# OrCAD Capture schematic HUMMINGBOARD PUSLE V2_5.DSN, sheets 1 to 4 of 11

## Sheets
1 POWER: size C; title: POWER; rev: 2.5.0
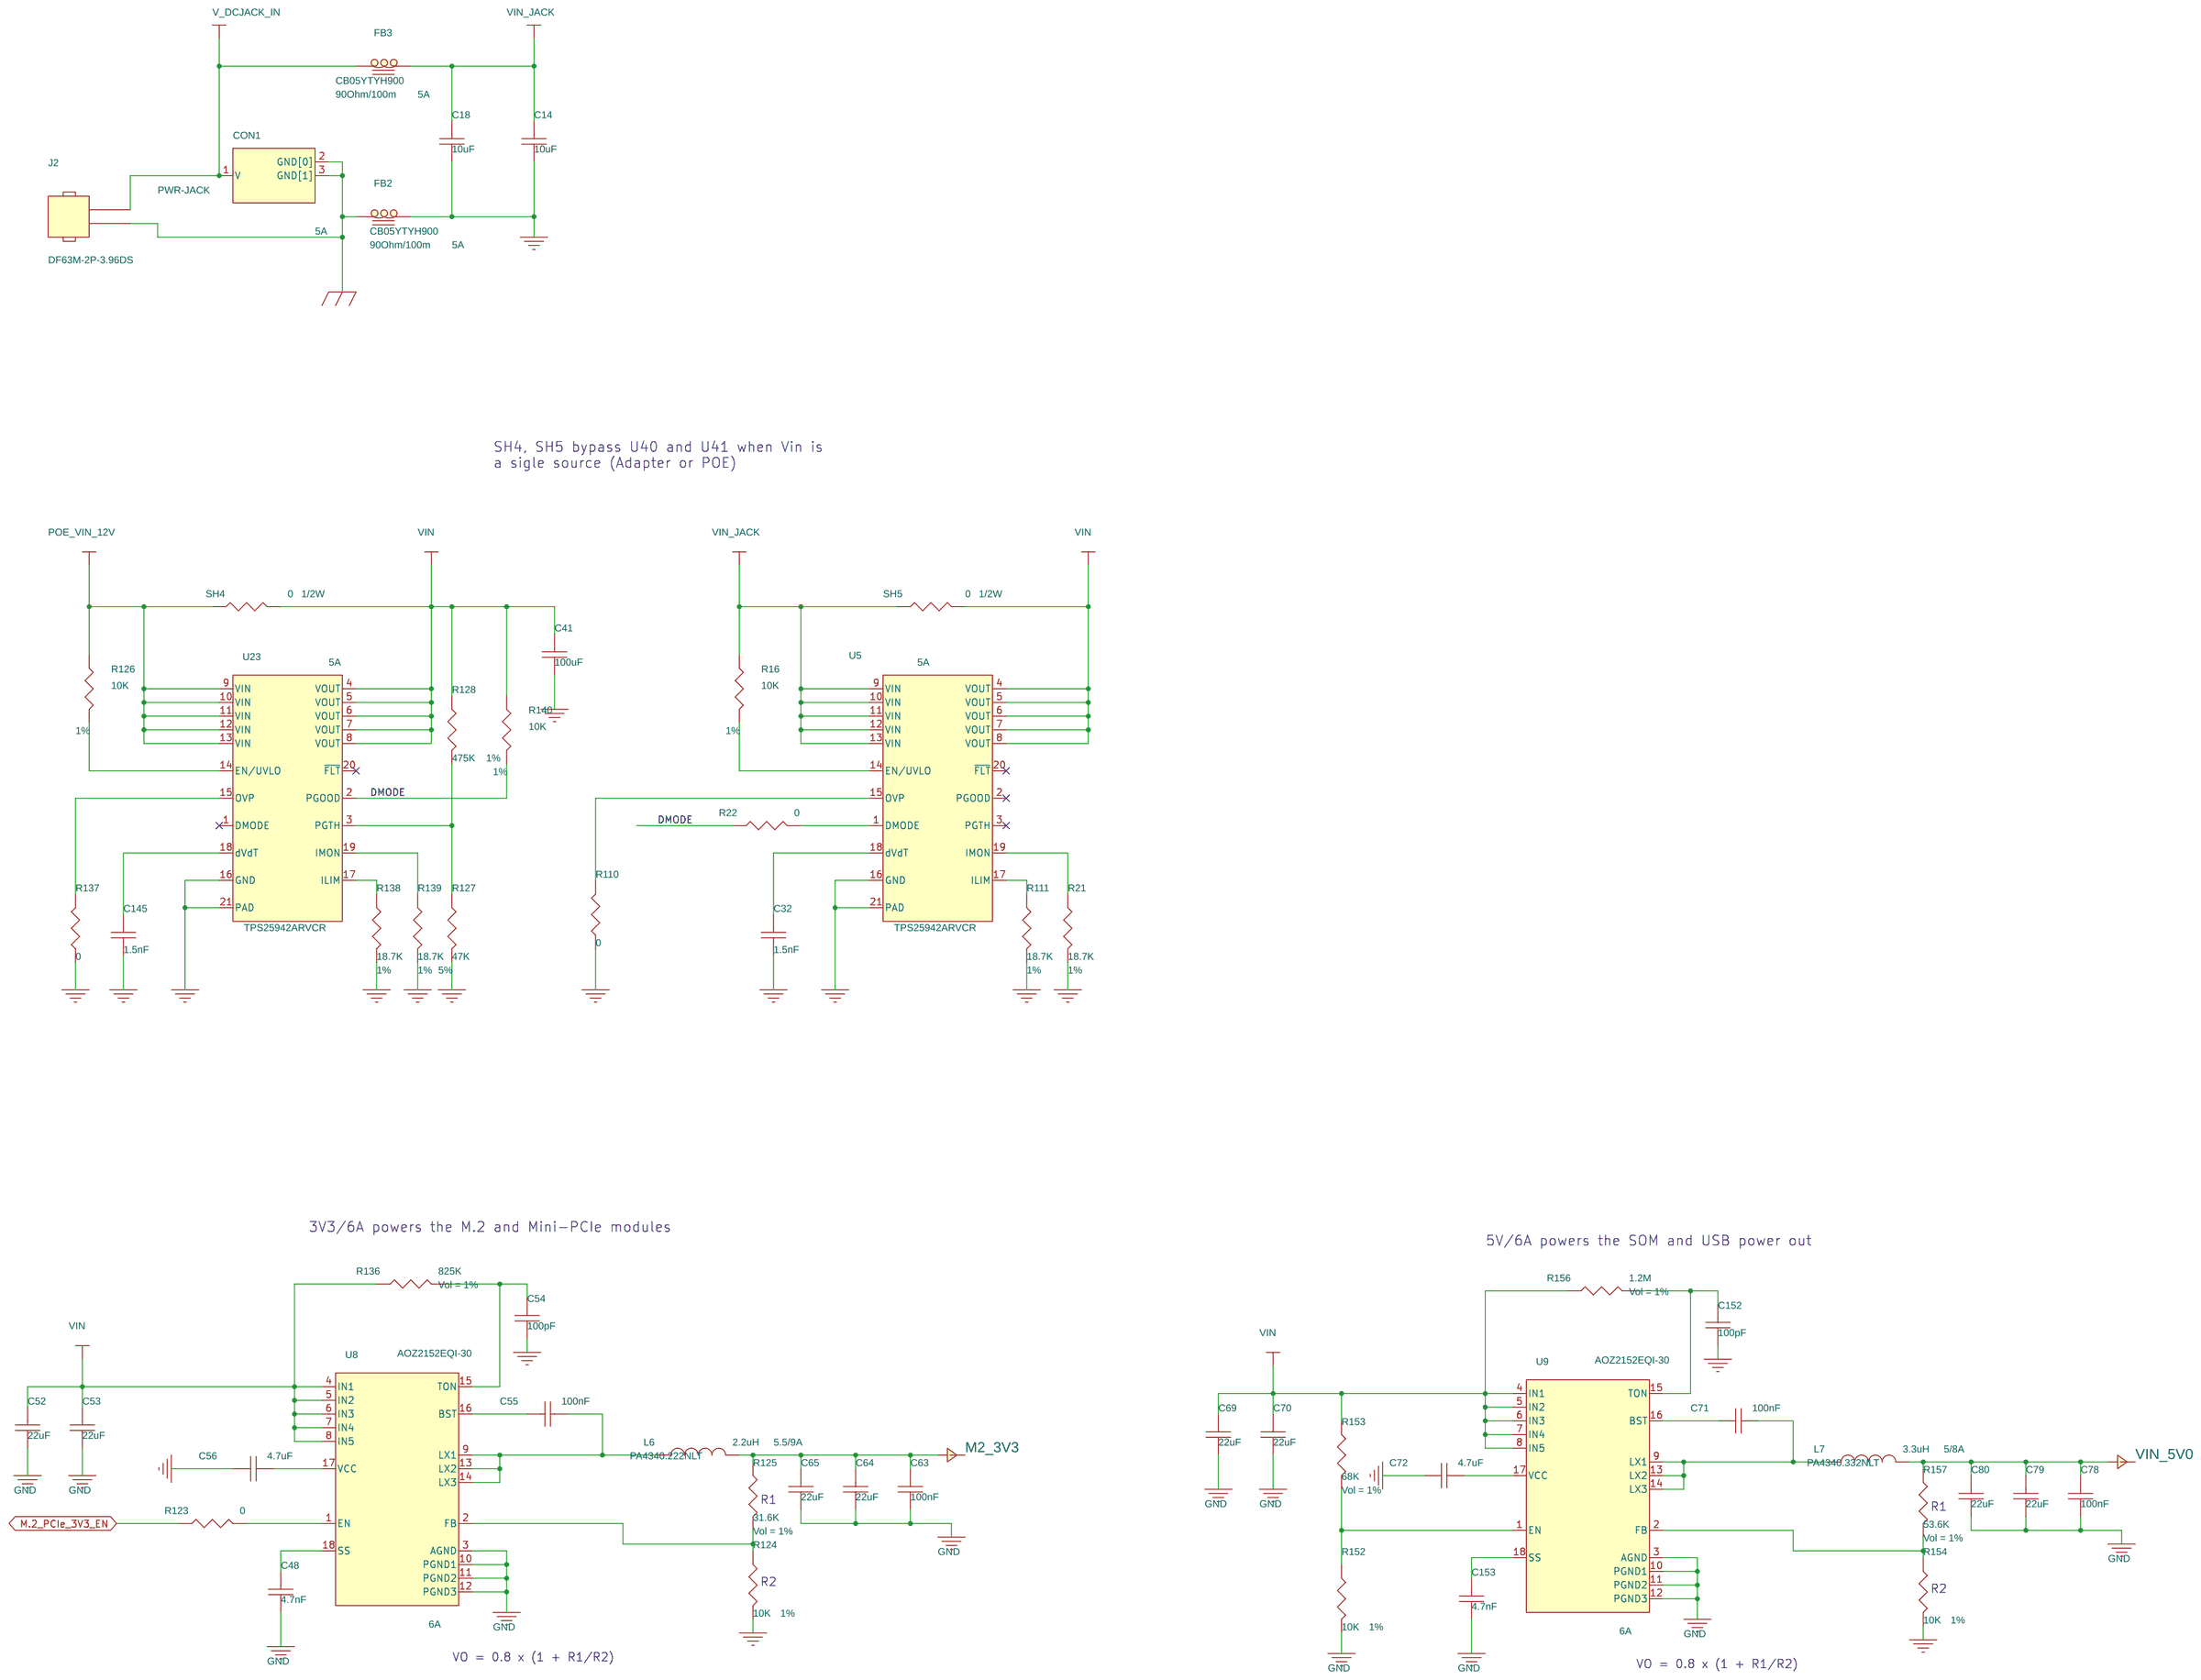
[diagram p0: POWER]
2 SYSTEM, ETHERNET, UART: size A3; title: SYSTEM,  DEBUG, uSD, EEPROM
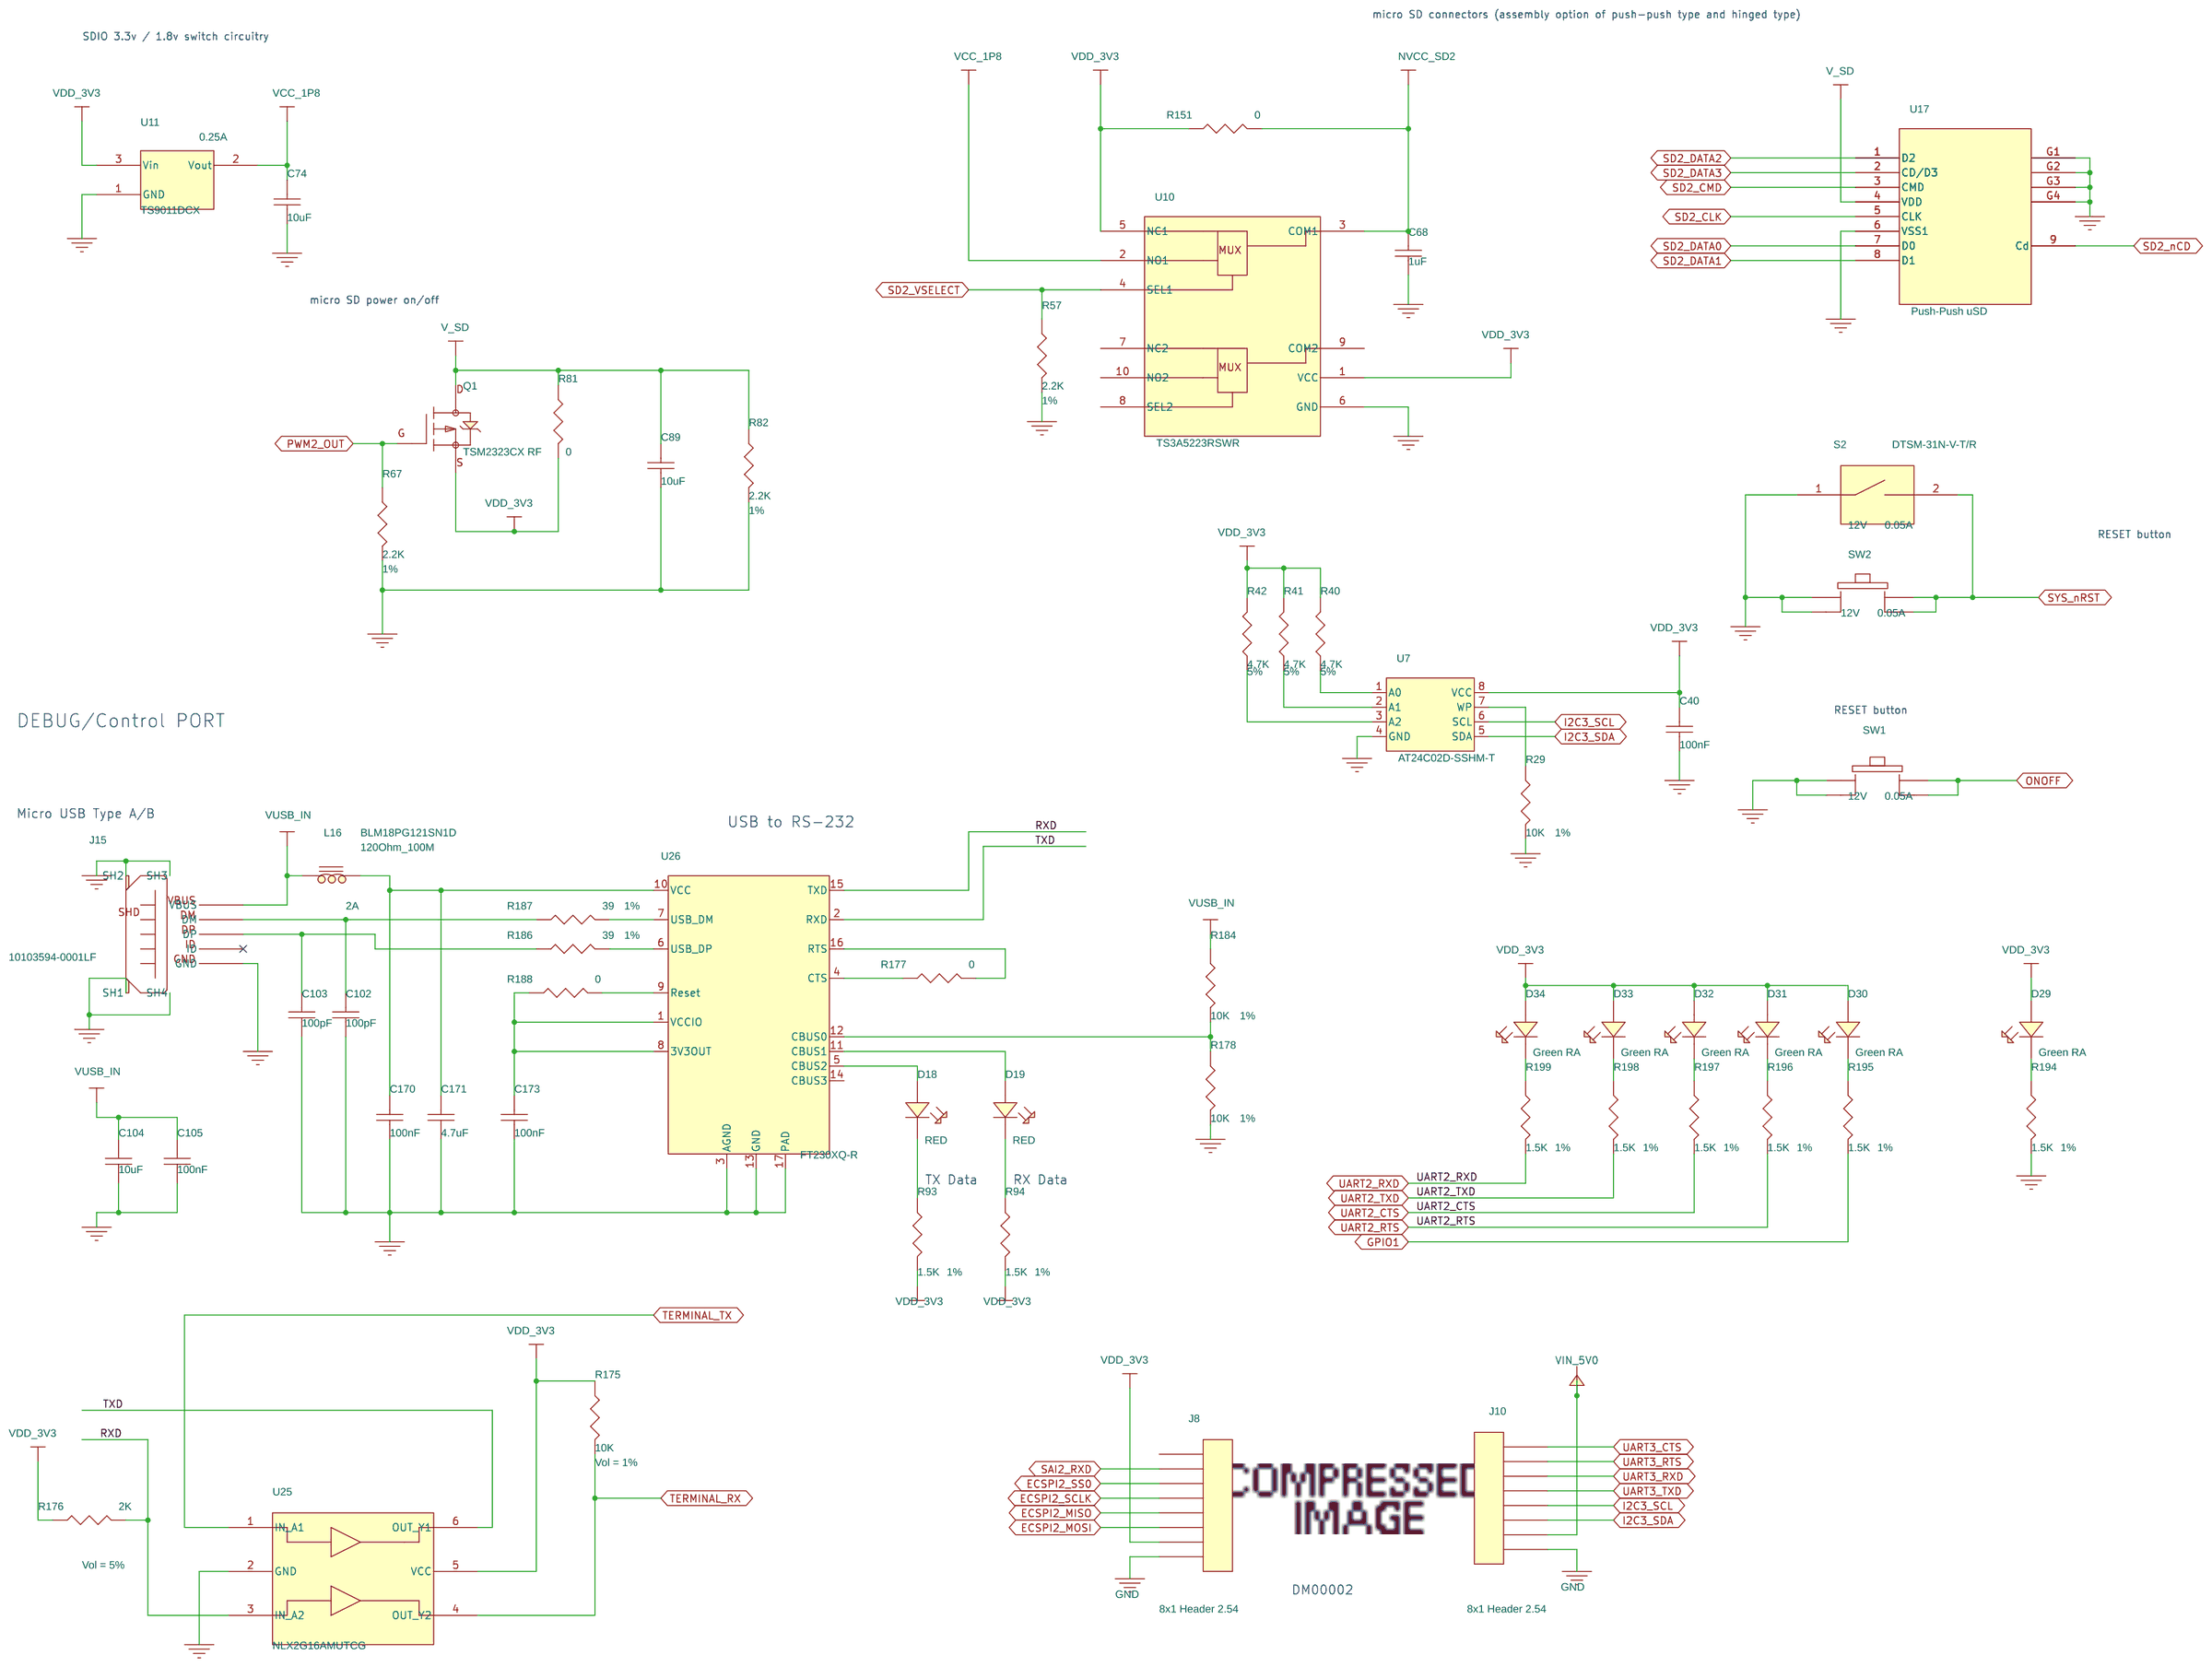
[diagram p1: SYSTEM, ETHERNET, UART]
3 PCIe, M.2, RTC: size A3; title: PCIE, M.2, RTC, IR
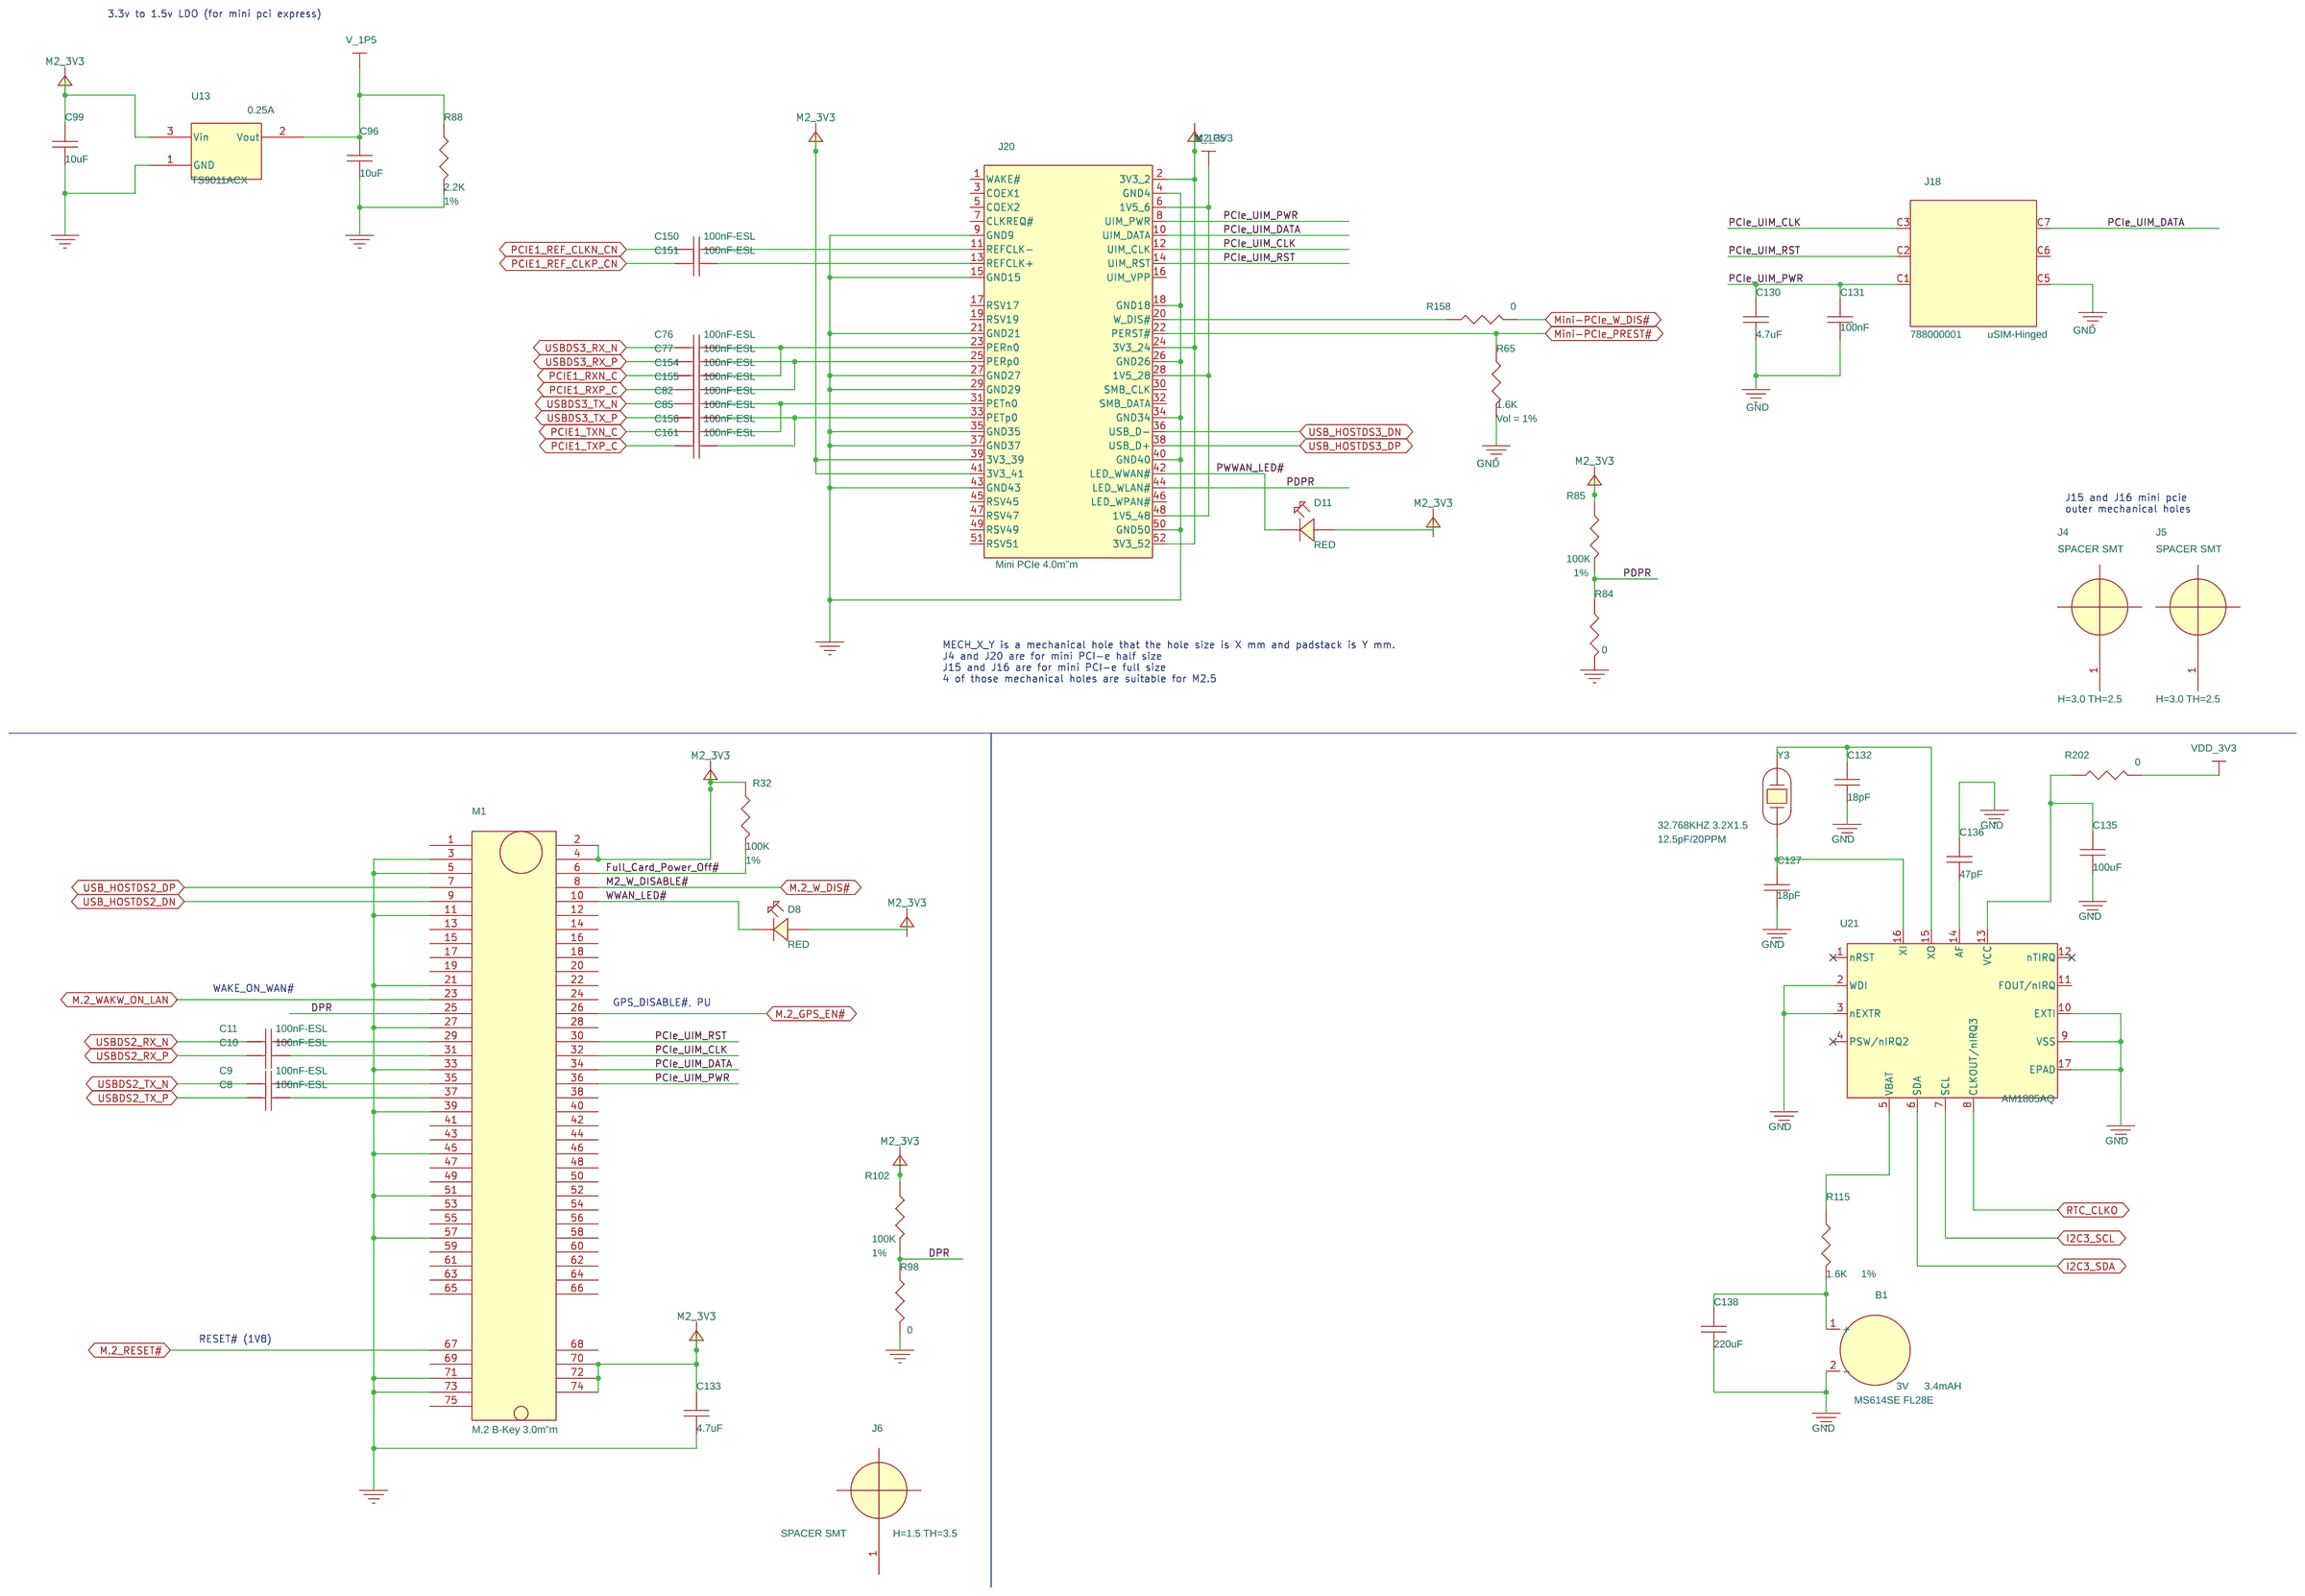
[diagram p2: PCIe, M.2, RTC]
4 USB HUB: size C; title: USB-3 HIB; rev: 2.4.0
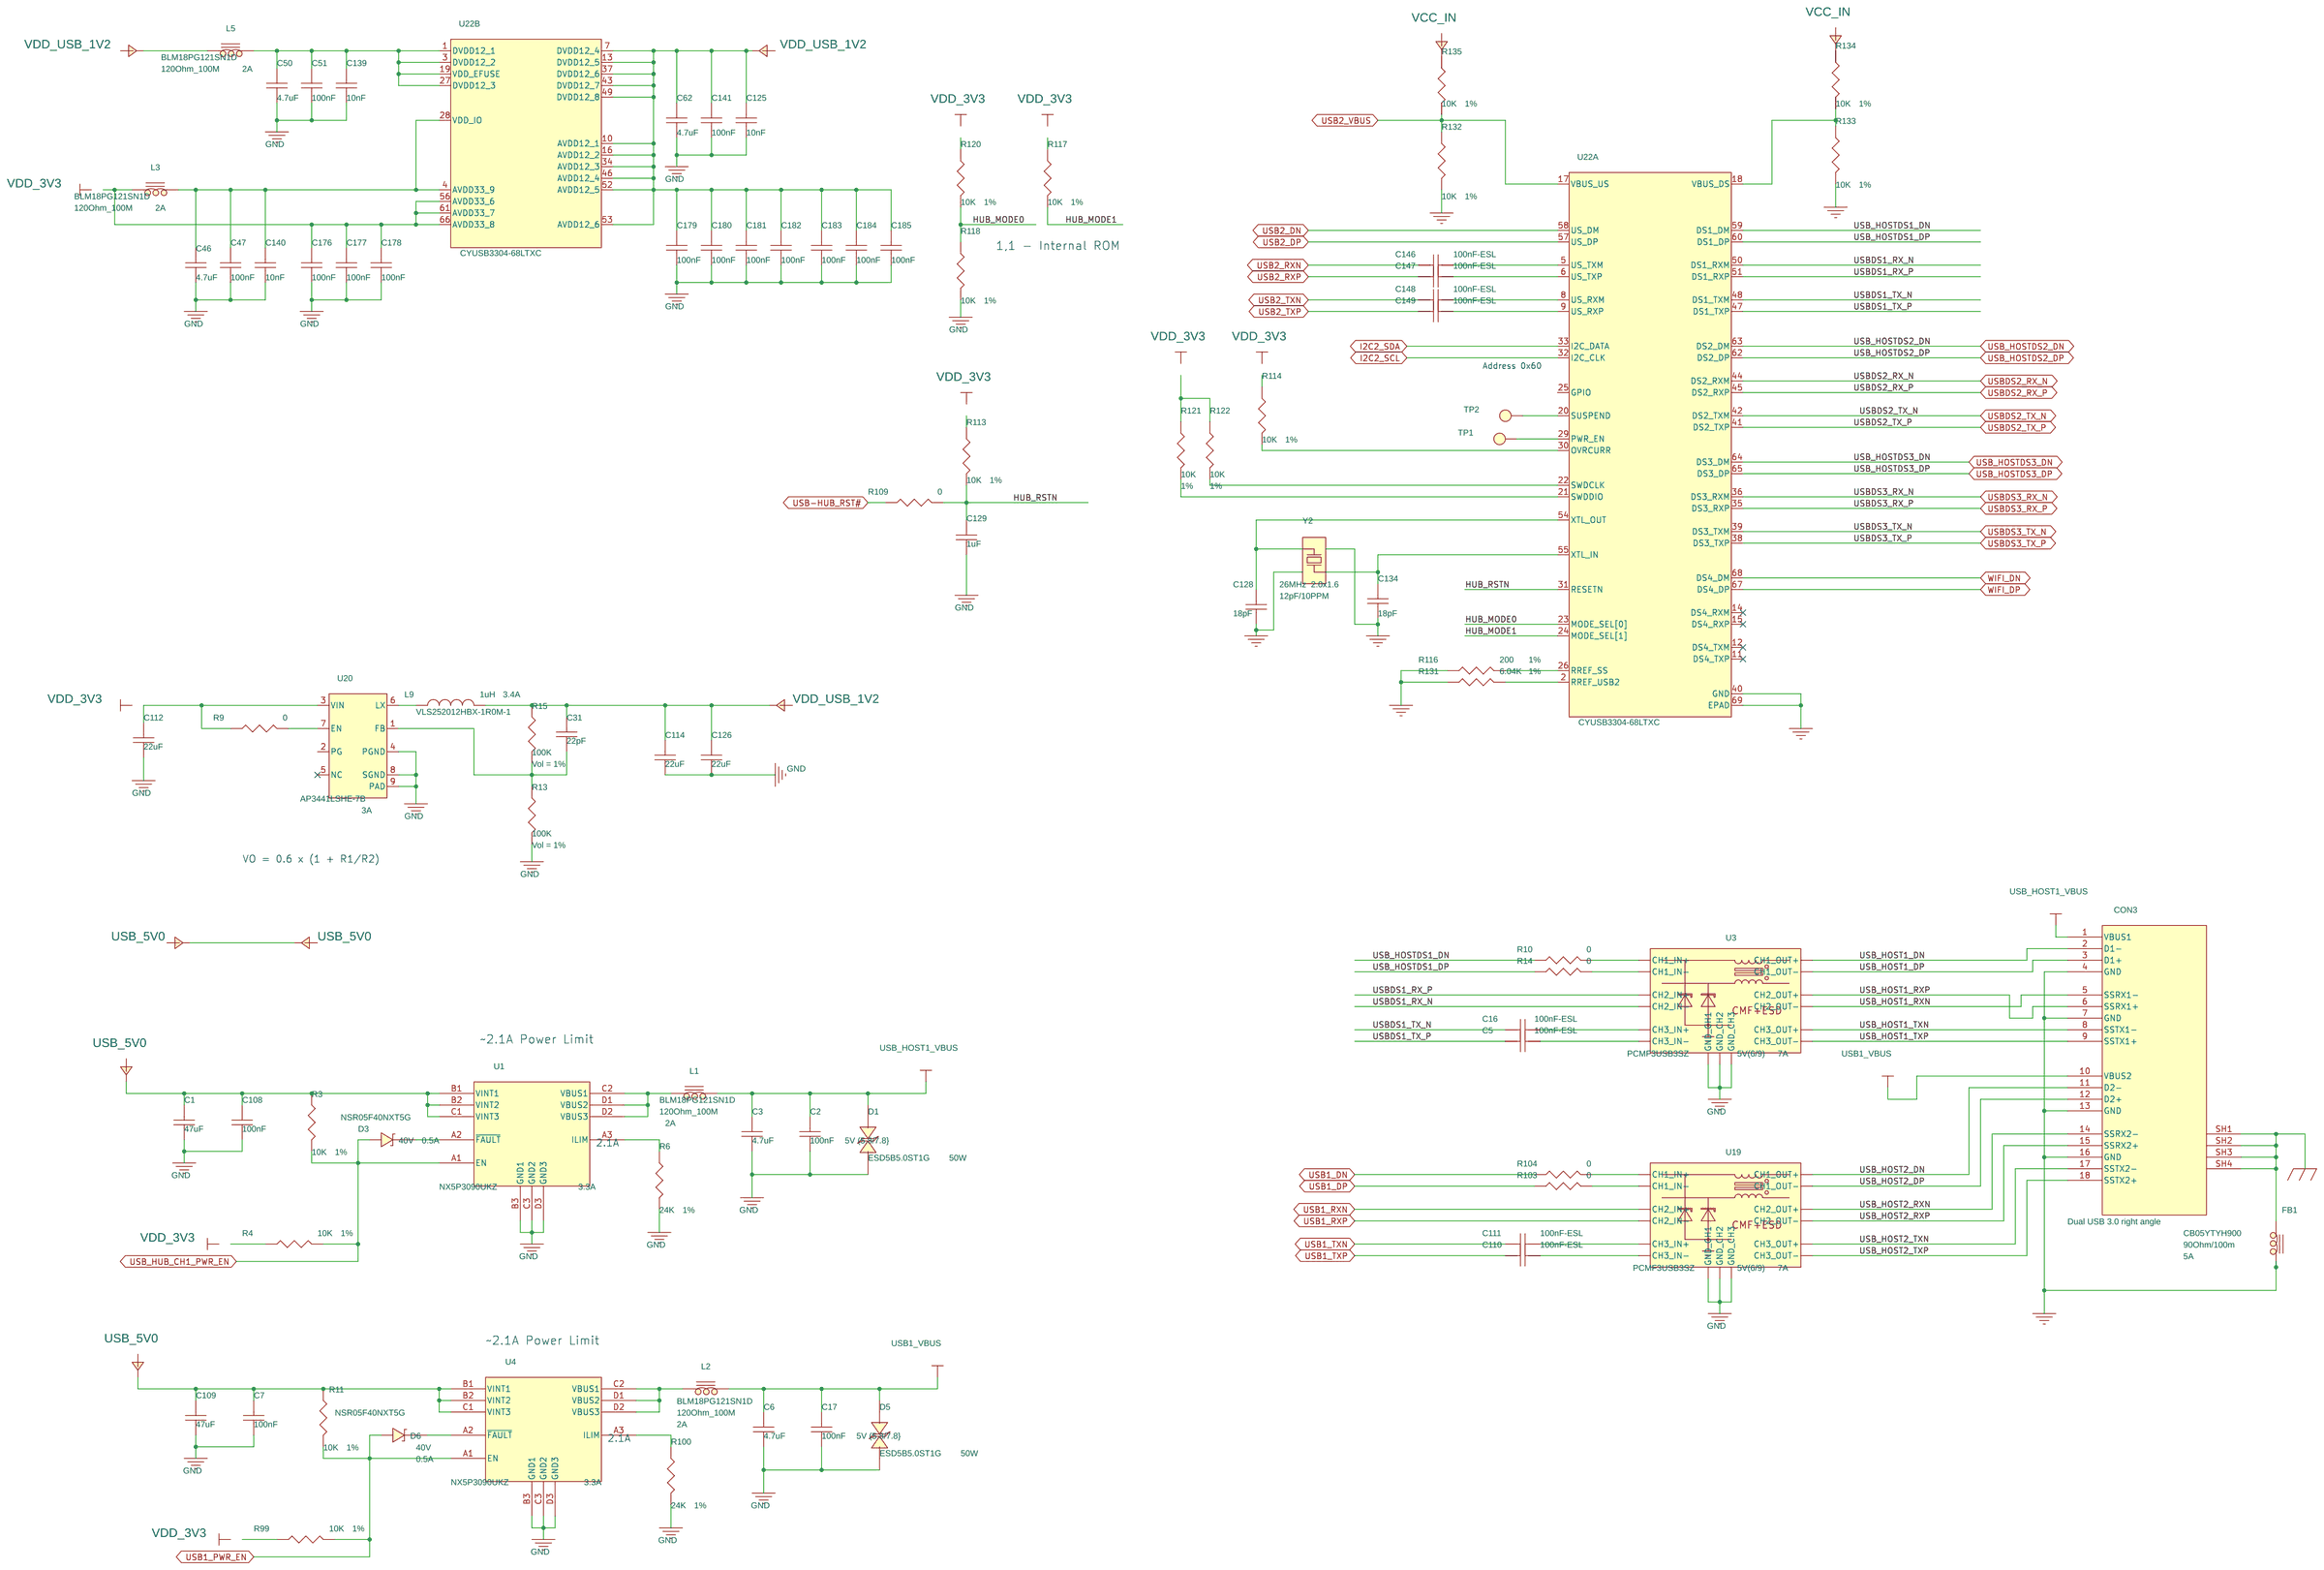
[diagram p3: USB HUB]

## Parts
sheet PCIe, M.2, RTC
B1  MS614SE FL28E  [MS614SE FL28E]
C8  100nF-ESL  [C0402]
C9  100nF-ESL  [C0402]
C10  100nF-ESL  [C0402]
C11  100nF-ESL  [C0402]
C76  100nF-ESL  [C0402]
C77  100nF-ESL  [C0402]
C82  100nF-ESL  [C0402]
C85  100nF-ESL  [C0402]
C96  10uF  [C0603]
C99  10uF  [C0603]
C127  18pF  [C0402]
C130  4.7uF  [C0603]
C131  100nF  [C0402]
C132  18pF  [C0402]
C133  4.7uF  [C0603]
C135  100uF  [C1210]
C136  47pF  [C0402]
C138  220uF  [C1210]
C150  100nF-ESL  [C0402]
C151  100nF-ESL  [C0402]
C154  100nF-ESL  [C0402]
C155  100nF-ESL  [C0402]
C156  100nF-ESL  [C0402]
C161  100nF-ESL  [C0402]
D8  RED  [1SA0603S11A0CB01]
D11  RED  [1SA0603S11A0CB01]
J4  SPACER SMT
J5  SPACER SMT
J6  SPACER SMT
J18  788000001  [788000001]
J20  Mini PCIe 4.0m"m  [MM60-52B1-G1-R850]
M1  M.2 B-Key 3.0m"m  [AS0BC21-S30BB-7H]
R32  100K  [R0402]
R65  1.6K  [R0402]
R84  0  [R0402]
R85  100K  [R0402]
R88  2.2K  [R0402]
R98  0  [R0402]
R102  100K  [R0402]
R115  1.6K  [R0402]
R158  0  [R0402]
R202  0  [R0603]
U13  TS9011ACX  [TS9011ACX]
U21  AM1805AQ  [AM1805AQ]
Y3  32.768KHZ 3.2X1.5  [NX3215SA32.768K-STD-MUA-4]
sheet POWER
C14  10uF  [C1206]
C18  10uF  [C1206]
C32  1.5nF  [C0402]
C41  100uF  [C1210]
C48  4.7nF  [C0402]
C52  22uF  [C1206]
C53  22uF  [C1206]
C54  100pF  [C0402]
C55  100nF  [C0402]
C56  4.7uF  [C0603]
C63  100nF  [C0402]
C64  22uF  [C0603]
C65  22uF  [C0603]
C69  22uF  [C1206]
C70  22uF  [C1206]
C71  100nF  [C0402]
C72  4.7uF  [C0603]
C78  100nF  [C0402]
C79  22uF  [C0603]
C80  22uF  [C0603]
C145  1.5nF  [C0402]
C152  100pF  [C0402]
C153  4.7nF  [C0402]
CON1  PWR-JACK  [KLDHCX-0202-A-LT]
FB2  CB05YTYH900  [CB05YTYH900]
FB3  CB05YTYH900  [CB05YTYH900]
J2  DF63M-2P-3.96DS  [DF63M-2P-3.96DS]
L6  PA4340.222NLT  [PA4340.222NLT]
L7  PA4340.332NLT  [PA4340.332NLT]
R16  10K  [R0402]
R21  18.7K  [R0402]
R22  0  [R0402]
R110  0  [R0402]
R111  18.7K  [R0402]
R123  0  [R0402]
R124  10K  [R0402]
R125  31.6K  [R0402]
R126  10K  [R0402]
R127  47K  [R0402]
R128  475K  [R0402]
R136  825K  [R0402]
R137  0  [R0402]
R138  18.7K  [R0402]
R139  18.7K  [R0402]
R140  10K  [R0402]
R152  10K  [R0402]
R153  68K  [R0402]
R154  10K  [R0402]
R156  1.2M  [R0402]
R157  53.6K  [R0402]
SH4  0  [R0603]
SH5  0  [R0603]
U5  TPS25942ARVCR  [TPS25942ARVCR]
U8  AOZ2152EQI-30  [AOZ2152EQI-30]
U9  AOZ2152EQI-30  [AOZ2152EQI-30]
U23  TPS25942ARVCR  [TPS25942ARVCR]
sheet SYSTEM, ETHERNET, UART
C40  100nF  [C0402]
C68  1uF  [C0402]
C74  10uF  [C0603]
C89  10uF  [C0603]
C102  100pF  [C0402]
C103  100pF  [C0402]
C104  10uF  [C0603]
C105  100nF  [C0402]
C170  100nF  [C0402]
C171  4.7uF  [C0603]
C173  100nF  [C0402]
D18  RED  [1SA0603S11A0CB01]
D19  RED  [1SA0603S11A0CB01]
D29  Green RA  [APA2106CGCK]
D30  Green RA  [APA2106CGCK]
D31  Green RA  [APA2106CGCK]
D32  Green RA  [APA2106CGCK]
D33  Green RA  [APA2106CGCK]
D34  Green RA  [APA2106CGCK]
J8  8x1 Header 2.54  [CH31082V200-NH]
J10  8x1 Header 2.54  [CH31082V200-NH]
J15  10103594-0001LF  [10103594-0001LF]
L16  BLM18PG121SN1D  [BLM18PG121SN1D]
Q1  TSM2323CX RF  [TSM2323CX RF]
R29  10K  [R0402]
R40  4.7K  [R0402]
R41  4.7K  [R0402]
R42  4.7K  [R0402]
R57  2.2K  [R0402]
R67  2.2K  [R0402]
R81  0  [R0402]
R82  2.2K  [R0402]
R93  1.5K  [R0402]
R94  1.5K  [R0402]
R151  0  [R0402]
R175  10K  [R0402]
R176  2K  [R0402]
R177  0  [R0402]
R178  10K  [R0402]
R184  10K  [R0402]
R186  39  [R0402]
R187  39  [R0402]
R188  0  [R0402]
R194  1.5K  [R0402]
R195  1.5K  [R0402]
R196  1.5K  [R0402]
R197  1.5K  [R0402]
R198  1.5K  [R0402]
R199  1.5K  [R0402]
S2  DTSM-31N-V-T/R  [DTSM-31N-V-T/R]
SW1  SKSCLDE010  [SKSCLDE010]
SW2  SKSCLDE010  [SKSCLDE010]
U7  AT24C02D-SSHM-T  [AT24C02D-SSHM-B]
U10  TS3A5223RSWR  [TS3A5223RSWR]
U11  TS9011DCX  [TS9011DCX]
U17  Push-Push uSD  [ZM90-15000-0BR1]
U25  NLX2G16AMUTCG  [NLX2G16AMUTCG]
U26  FT230XQ-R  [FT230XQ-R]
sheet USB HUB
C1  47uF  [C1206]
C2  100nF  [C0402]
C3  4.7uF  [C0603]
C5  100nF-ESL  [C0402]
C6  4.7uF  [C0603]
C7  100nF  [C0402]
C16  100nF-ESL  [C0402]
C17  100nF  [C0402]
C31  22pF  [C0402]
C46  4.7uF  [C0603]
C47  100nF  [C0402]
C50  4.7uF  [C0603]
C51  100nF  [C0402]
C62  4.7uF  [C0603]
C108  100nF  [C0402]
C109  47uF  [C1206]
C110  100nF-ESL  [C0402]
C111  100nF-ESL  [C0402]
C112  22uF  [C0603]
C114  22uF  [C0603]
C125  10nF  [C0402]
C126  22uF  [C0603]
C128  18pF  [C0402]
C129  1uF  [C0402]
C134  18pF  [C0402]
C139  10nF  [C0402]
C140  10nF  [C0402]
C141  100nF  [C0402]
C146  100nF-ESL  [C0402]
C147  100nF-ESL  [C0402]
C148  100nF-ESL  [C0402]
C149  100nF-ESL  [C0402]
C176  100nF  [C0402]
C177  100nF  [C0402]
C178  100nF  [C0402]
C179  100nF  [C0402]
C180  100nF  [C0402]
C181  100nF  [C0402]
C182  100nF  [C0402]
C183  100nF  [C0402]
C184  100nF  [C0402]
C185  100nF  [C0402]
CON3  Dual USB 3.0 right angle  [U3AFR03-B-P/L-B-G0-A]
D1  ESD5B5.0ST1G  [ESD5B5.0ST1G]
D3  NSR05F40NXT5G  [NSR05F40NXT5G]
D5  ESD5B5.0ST1G  [ESD5B5.0ST1G]
D6  NSR05F40NXT5G  [NSR05F40NXT5G]
FB1  CB05YTYH900  [CB05YTYH900]
L1  BLM18PG121SN1D  [BLM18PG121SN1D]
L2  BLM18PG121SN1D  [BLM18PG121SN1D]
L3  BLM18PG121SN1D  [BLM18PG121SN1D]
L5  BLM18PG121SN1D  [BLM18PG121SN1D]
L9  VLS252012HBX-1R0M-1  [VLS252012HBX-1R0M-1]
R3  10K  [R0402]
R4  10K  [R0402]
R6  24K  [R0402]
R9  0  [R0402]
R10  0  [R0402]
R11  10K  [R0402]
R13  100K  [R0402]
R14  0  [R0402]
R15  100K  [R0402]
R99  10K  [R0402]
R100  24K  [R0402]
R103  0  [R0402]
R104  0  [R0402]
R109  0  [R0402]
R113  10K  [R0402]
R114  10K  [R0402]
R116  200  [R0402]
R117  10K  [R0402]
R118  10K  [R0402]
R120  10K  [R0402]
R121  10K  [R0402]
R122  10K  [R0402]
R131  6.04K  [R0402]
R132  10K  [R0402]
R133  10K  [R0402]
R134  10K  [R0402]
R135  10K  [R0402]
TP1  R 35
TP2  R 35
U1  NX5P3090UKZ  [NX5P3090UKZ]
U3  PCMF3USB3SZ  [PCMF3USB3SZ]
U4  NX5P3090UKZ  [NX5P3090UKZ]
U19  PCMF3USB3SZ  [PCMF3USB3SZ]
U20  AP3441LSHE-7B  [AP3441LSHE-7B]
U22  CYUSB3304-68LTXC  [CYUSB3304-68LTXC]  (sections A,B)
Y2  26MHz  2.0x1.6  [FA-128 26.0000MF10Z-W5]

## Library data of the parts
B1 = BAT-MS621FE: BATT LITH 3V 3.4MAH COIN 6.8MM; Category : Battery-RCH; Digikey P/N: 728-1055-ND; Manufacturer: Seiko Instruments; Rating: 3.4mAH; SolidRun P/N: BT00007; Vol: 3V; Datasheet: https://www.sii.co.jp/en/me/files/2017/04/MicroBatteryCatalogue-E_2017_web.pdf
C5 C8-C11 C16 C76 C77 C82 C85 C110 C111 C146-C151 C154-C156 C161 = CAP_NP1: CAP CER 0.1uF ±10% 25V X7R 0402; Category : Capacitors (Size: 0402); Manufacturer: CAPAX; Part Num#: 0402X104K250SNT; Rating: 25V; SolidRun P/N: CA20090; Vol: 10%
C74 C89 C96 C99 = CAP_NP1: CAP CER 10uF ±10% 6.3V X5R 0603; Category : Capacitors (Size: 0603); Digikey P/N: 1276-1038-1-ND; Manufacturer: Samsung Electro-Mechanics; Part Num#: CL10A106KQ8NNNC; Rating: 6.3V; SolidRun P/N: CA30001; Vol: 10%
C127 C128 C132 C134 = CAP_NP1: CAP CER 18pF ±1% 50V C0G/NPO 0402; Category : Capacitors (Size: 0402); Digikey P/N: 311-1643-1-ND; Manufacturer: YAGEO; Part Num#: CC0402FRNPO9BN180; Rating: 50V; SolidRun P/N: CA20017; Vol: 1%
C46 C50 C62 C130 C133 = CAP_NP1: CAP CER 4.7uF ±10% 6.3V X5R; Category : Capacitors (Size: 0603); Digikey P/N: 1276-1045-2-ND; Manufacturer: Samsung Electro-Mechanics; Part Num#: CL10A475KQ8NNNC; Rating: 6.3V; SolidRun P/N: CA30003; Vol: 10%
C2 C7 C17 C40 C47 C51 C105 C108 C131 C141 C170 C173 C176-C185 = CAP_NP1: CAP CER 0.1uF ±10% 16V X7R 0402; Category : Capacitors (Size: 0402); Digikey P/N: 1276-1001-1-ND; Manufacturer: Samsung Electro-Mechanics; Part Num#: CL05B104KO5NNNC; Rating: 16V; SolidRun P/N: CA20013; Vol: 10%
C135 = CAP_NP1: CAP CER 100uF ±20% 16V X5R 1210; Category : Capacitors (Size: 0603); Digikey P/N: 311-2052-1-ND; Manufacturer: YAGEO; Part Num#: CC1210MKX5R7BB107; Rating: 16V; SolidRun P/N: CA60008; Vol: 20%
C136 = CAP_NP1: CAP CER 47pF ±5% 50V C0G/NP0 0402; Category : Capacitors (Size: 0402); Digikey P/N: 490-1287-6-ND; Manufacturer: Murata Electronics North America; Part Num#: GRM1555C1H470JZ01D; Rating: 50V; SolidRun P/N: CA20144; Vol: 5%
C138 = CAP_NP1: CAP CER 220uF ±20% 6.3V X5R 1210; Category : Capacitors (Size: 1210); Digikey P/N: 1276-3375-1-ND; Manufacturer: Samsung Electro-Mechanics; Part Num#: CL32A227MQVNNNE; Rating: 6.3V; SolidRun P/N: CA60007; Vol: 20%
D8 D11 D18 D19 = LED: Indication LED 0603 - Red; Category : DI-LED; Manufacturer: BRIGHTEK; Rating: 0.02A; SolidRun P/N: DI00007; Vol: 2V
J4 J5 = SPACER_SMT: SPACER H=3MM TH=2.5; Category : MECH-SPACER; Manufacturer: A-LINK; Part Num#: S0305025A; SolidRun P/N: MCH0006; Vol: H=3.0 TH=2.5; Datasheet: http://www.alink.com.tw/smt%20fastener%20standard%20parts.html
J6 = SPACER_SMT: 1.5mm metal spacer for M.2.5 connector 3.5mm / 5.1mm (3.7mm / 6.0mm hole); Category: MECH-SPACER; Category : MECHANICAL PARTS; Digikey P/N: 732-7068-2-ND; Manufacturer: Wurth Elektronik; Part Num#: WE 977-401-515-1R; SolidRun P/N: MCH0008; Vol: H=1.5 TH=3.5; Datasheet: http://katalog.we-online.de/em/datasheet/9774015151R.pdf
J18 = J-uSIM_CARD_HOLDER_x_6: CONN MICRO SIM CARD HINGED TYPE; Category : CON-Usd/SIM; Digikey P/N: WM9786TR-ND; Manufacturer: Molex, LLC; SolidRun P/N: CO00653; VOL: uSIM-Hinged; Datasheet: https://www.molex.com/pdm_docs/sd/788000001_sd.pdf
J20 = J-Mini_PCIe: mini PCIe connector without thru hole standoffs to hold the card (CO00018 compatible); Category : CON-PCIe/SATA/M.2; Digikey P/N: 670-2516-1-ND; Manufacturer: JAE Electronics; SolidRun P/N: CO00647; Datasheet: http://www.jae.com/z-en/pdf_download_exec.cfm?param=SJ110608.pdf
M1 = M-NGFF_M.2: NGFF M.2 SSD connector with 2242 matching hole - 3.0H Key B; Category: CON-PCIe/SATA/M.2; Category : CON-PCIe/SATA/M.2; Manufacturer: Foxconn; SolidRun P/N: CO00595; Datasheet: http://www.fit-foxconn.com/Product/ProductDetail?topClassID=&&PN=AS0BC21-S30BB-7H
R32 R85 R102 = RES1: RES SMD 100K OHM 1% 1/16W 0402; Category : Resistors (Size: 0402); Digikey P/N: 311-100KLRCT-ND; Manufacturer: YAGEO; Part Num#: RC0402FR-07100KL; Rating: 1/16W; SolidRun P/N: RE20482; Vol: 1%
R65 = RES1: RES SMD 1.6K OHM 1% 1/16W 0402; Category: Resistors (Size: 0402); Digikey P/N: YAG3045CT-ND; Manufacturer: YAGEO; Part Num#: RC0402FR-071K6L; Rating: 1/16W; SolidRun P/N: RE20030; Vol: 1%
R9 R10 R14 R22 R81 R84 R98 R103 R104 R109 R110 R123 R137 R151 R158 R177 R188 = RES1: RES SMD 0 OHM JUMPER 1/16W 0402; Category : Resistors (Size: 0402); Digikey P/N: 311-0.0JRCT-ND; Manufacturer: YAGEO; Part Num#: RC0402JR-070RL; Rating: 1/16W; SolidRun P/N: RE20009
R57 R67 R82 R88 = RES1: RES SMD 2.2K OHM 1% 1/16W 0402; Category : Resistors (Size: 0402); Digikey P/N: 311-2.20KLRCT-ND; Manufacturer: YAGEO; Part Num#: RC0402FR-072K2L; Rating: 1/16W; SolidRun P/N: RE20204; Vol: 1%
R115 = RES1: RES SMD 1.6K OHM 1% 1/16W 0402; Category : Resistors (Size: 0402); Digikey P/N: YAG3045CT-ND; Manufacturer: YAGEO; Part Num#: RC0402FR-071K6L; Rating: 1/16W; SolidRun P/N: RE20030; Vol: 1%
R202 = RES1: RES SMD 0 OHM JUMPER 1/10W 0603; Digikey P/N: 311-0.0GRCT-ND; Manufacturer: YAGEO; Part Num#: RC0603JR-070RL; Rating: 1/10W; SolidRun P/N: RE30006
U13 = IC-TS9011ACX: "LDO - 1.5v output, 0.25A, 12V maximum in"; Category : IC-PWR-LDO; Manufacturer: Taiwan Semiconductor Corporation; Rating: 0.25A; SolidRun P/N: IC00161; VOL: 1.5V
U21 = IC-AM1805: REAL-TIME CLOCK WITH POWER MANAG; Category : IC-RTC; Digikey P/N: 1822-1006-2-ND; Manufacturer: Ambiq Micro, Inc.; SolidRun P/N: IC01186; Datasheet: http://ambiqmicro.com/wp-content/uploads/2016/11/am18x5_data_sheet_ds0003v1p2.pdf
Y3 = XTAL-2P: XTAL 32.768KHZ 12.5PF 20PPM 3.2X1.5MM SM; Category : OC-CRYSTAL; Manufacturer: NDK; Rating: 12.5pF/20PPM; SolidRun P/N: OC00001; Datasheet: http://www.ndk.com/images/products/catalog/c_NX3215SA_e.pdf
C14 C18 = CAP_NP1: CAP CER 10uF ±10% 50V X5R 1206; Category : Capacitors (Size: 1206); Digikey P/N: 490-5961-1-ND; Manufacturer: Murata Electronics North America; Part Num#: GRM31CR61H106KA12L; Rating: 50V; SolidRun P/N: CA50004; Vol: 10%
C32 C145 = CAP_NP1: CAP CER 1.5nF ±5% 50V X7R 0402; Category : Capacitors (Size: 0402); Digikey P/N: 490-10779-2-ND; Manufacturer: Murata Electronics North America; Part Num#: GRM155R71H152JA01D; Rating: 50V; SolidRun P/N: CA20138; Vol: 5%
C41 = CAP_NP1: CAP CER 100uF ±20% 16V X5R 1210; Category : Capacitors (Size: 1210); Digikey P/N: 311-2052-1-ND; Manufacturer: YAGEO; Part Num#: CC1210MKX5R7BB107; Rating: 16V; SolidRun P/N: CA60008; Vol: 20%
C48 C153 = CAP_NP1: CAP CER 4.7nF ±10% 25V X7R 0402; Category: Capacitors (Size: 0402); Digikey P/N: 1276-1571-1-ND; Manufacturer: Samsung Electro-Mechanics; Part Num#: CL05B472KA5NNNC; Rating: 25V; SolidRun P/N: CA20802; Vol: 10%
C52 C53 C69 C70 = CAP_NP1: 22µF ±20% 35V Ceramic Capacitor X5R 1206 (3216 Metric); Category: Capacitors (Size: 1206); Digikey P/N: 445-8045-2-ND; Manufacturer: TDK Corporation; Part Num#: C3216X5R1V226M160AC; Rating: 35V; SolidRun P/N: CA50012; Vol: 20%
C54 C102 C103 C152 = CAP_NP1: CAP CER 100pF 50V 5% C0G 0402; Category : Capacitors (Size: 0402); Digikey P/N: 1276-1025-2-ND; Manufacturer: Samsung Electro-Mechanics; Part Num#: CL05C101JB5NNNC; Rating: 50V; SolidRun P/N: CA20006; Vol: 5%
C55 C63 C71 C78 = CAP_NP1: CAP CER 0.1uF ±10% 16V X7R 0402; Category: Capacitors (Size: 0402); Digikey P/N: 1276-1001-1-ND; Manufacturer: Samsung Electro-Mechanics; Part Num#: CL05B104KO5NNNC; Rating: 16V; SolidRun P/N: CA20013; Vol: 10%
C56 C72 = CAP_NP1: CAP CER 4.7uF ±10% 6.3V X5R; Category: Capacitors (Size: 0603); Digikey P/N: 1276-1045-2-ND; Manufacturer: Samsung Electro-Mechanics; Part Num#: CL10A475KQ8NNNC; Rating: 6.3V; SolidRun P/N: CA30003; Vol: 10%
C64 C65 C79 C80 C112 C114 C126 = CAP_NP1: CAP CER 22uF ±20% 6.3V X5R 0603; Category: Capacitors (Size: 0603); Digikey P/N: 1276-2868-1-ND; Manufacturer: Samsung Electro-Mechanics; Part Num#: CL10A226MQ8NRNE; Rating: 6.3V; SolidRun P/N: CA30002; Vol: 20%
CON1 = J-POWER_JACK: High Current PCB Mount  DC Power Jack 2.0mm Center Pin Diameter  Locking Type; Category : CON-PWR; Manufacturer: Kycon Inc; Rating: 5A; SolidRun P/N: CO00053; VOL: 24V; Datasheet: https://www.mouser.co.il/datasheet/2/222/KLDHCX-0202-x-LT-1222695.pdf
FB1-FB3 = Ferrite_Bead: Filter Bead 90ohms 25% 0805 HighCurrent,RatedCurrent=3A; Category : COILS-FERRIT; Digikey P/N: 541-2303-2-ND; Manufacturer: VIKING; Rating: 5A; SolidRun P/N: IN00001; Vol: 90Ohm/100m; Datasheet: https://www.viking.com.tw/Templates/att/CBM_Series.pdf?lng=en
J2 = J-HEADER_2x1: Connector Header Through Hole, Right Angle 2 position 0.156" (3.96mm); Category: CON-HEADER; Digikey P/N: DF63M-2P-3.96DS-ND; Manufacturer: Hirose Electric Co Ltd; SolidRun P/N: CO00748; VOL: R/A POWER; Datasheet: https://www.hirose.com/product/document?clcode=CL0680-0567-0-00&productname=DF63M-2P-3.96DSA&series=DF63&documenttype=2DDrawing&lang=en&documentid=0001262566
L6 = INDUCTOR1: 2.2µH Shielded Molded Inductor 5.5A 35mOhm Max Nonstandard; Category: COILS-IND; Digikey P/N: 553-3393-2-ND; Manufacturer: Pulse Electronics Power; Rating: 5.5/9A; SolidRun P/N: IN00136; Vol: 2.2uH; Datasheet: http://productfinder.pulseeng.com/products/datasheets/P767.pdf
L7 = INDUCTOR1: 3.3µH Shielded Molded Inductor 5A 38mOhm Max Nonstandard; Category: COILS-IND; Digikey P/N: 553-3396-1-ND; Manufacturer: Pulse Electronics Power; Rating: 5/8A; SolidRun P/N: IN00135; Vol: 3.3uH; Datasheet: http://productfinder.pulseeng.com/products/datasheets/P767.pdf
R3 R4 R11 R16 R29 R99 R113 R114 R117 R118 R120-R122 R126 R132-R135 R140 R152 R178 R184 = RES1: RES SMD 10K OHM 1% 1/16W 0402; Category : Resistors (Size: 0402); Digikey P/N: 311-10.0KLRCT-ND; Manufacturer: YAGEO; Part Num#: RC0402FR-0710KL; Rating: 1/16W; SolidRun P/N: RE20013; Vol: 1%
R21 R111 R138 R139 = RES1: RES SMD 18.7K OHM 1% 1/16W 0402; Category : Resistors (Size: 0402); Digikey P/N: YAG3018CT-ND; Manufacturer: YAGEO; Part Num#: RC0402FR-0718K7L; Rating: 1/16W; SolidRun P/N: RE20017; Vol: 1%
R124 R154 R175 = RES1: RES SMD 10K OHM 1% 1/16W 0402; Category: Resistors (Size: 0402); Digikey P/N: 311-10.0KLRCT-ND; Manufacturer: YAGEO; Part Num#: RC0402FR-0710KL; Rating: 1/16W; SolidRun P/N: RE20013; Vol: 1%
R125 = RES1: RES SMD 31.6K OHM 1% 1/16W 0402; Category: Resistors (Size: 0402); Digikey P/N: YAG3115CT-ND; Manufacturer: YAGEO; Part Num#: RC0402FR-0731K6L; Rating: 1/16W; SolidRun P/N: RE20023; Vol: 1%
R127 = RES1: RES SMD 47K OHM 5% 1/16W 0402; Category : Resistors (Size: 0402); Digikey P/N: 311-47KJRCT-ND; Manufacturer: YAGEO; Part Num#: RC0402JR-0747KL; Rating: 1/16W; SolidRun P/N: RE20012; Vol: 5%
R128 = RES1: RES SMD 475K OHM 1% 1/16W 0402; Category : Resistors (Size: 0402); Digikey P/N: 311-475KLRCT-ND; Manufacturer: YAGEO; Part Num#: RC0402FR-07475KL; Rating: 1/16W; SolidRun P/N: RE20018; Vol: 1%
R136 = RES1: RES SMD 825K OHM 1% 1/16W 0402; Category: Resistors (Size: 0402); Digikey P/N: YAG3241TR-ND; Manufacturer: YAGEO; Part Num#: RC0402FR-07825KL; Rating: 1/16W; SolidRun P/N: RE20522; Vol: 1%
R153 = RES1: RES SMD 68K OHM 1% 1/16W 0402; Category: Resistors (Size: 0402); Digikey P/N: 311-68.0KLRCT-ND; Manufacturer: YAGEO; Part Num#: RC0402FR-0768KL; Rating: 1/16W; SolidRun P/N: RE20104; Vol: 1%
R156 = RES1: RES SMD 1.2M OHM 1% 1/16W 0402; Category: Resistors (Size: 0402); Digikey P/N: 541-1.20MLCT-ND; Manufacturer: Vishay Dale; Part Num#: CRCW04021M20FKED; Rating: 1/16W; SolidRun P/N: RE20494; Vol: 1%
R157 = RES1: RES SMD 53.6K OHM 1% 1/16W 0402; Category: Resistors (Size: 0402); Digikey P/N: 311-53.6KLRCT-ND; Manufacturer: YAGEO; Part Num#: RC0402FR-0753K6L; Rating: 1/16W; SolidRun P/N: RE20020; Vol: 1%
SH4 SH5 = RES1: RES SMD 0 OHM JUMPER 1/2W 0603; Category : Resistors (Size: 0603); Digikey P/N: 36-5110CT-ND; Manufacturer: Keystone Electronics; Part Num#: 5110; Rating: 1/2W; SolidRun P/N: RE30017
U5 U23 = IC-TPS25942A: IC PWR MGMT EFUSE 2.7-18V 20WQFN; Category : IC-PWR-SW; Digikey P/N: 296-40735-2-ND; Manufacturer: Texas Instruments; Rating: 5A; SolidRun P/N: IC01221; VOL: 18V; Datasheet: http://www.ti.com/lit/ds/slvsce9d/slvsce9d.pdf
U8 U9 = IC-AOZ2152EQI: IC REG BUCK ADJ 6A 18QFN; Category: IC-PWR-BUCK; Digikey P/N: AOZ2152EQI-30-ND; Manufacturer: Alpha & Omega Semiconductor Inc.; Rating: 6A; SolidRun P/N: IC01410; VOL: 28V; Datasheet: http://aosmd.com/res/data_sheets/AOZ2152EQI-30.pdf
C68 C129 = CAP_NP1: CAP CER 1UF 10V X5R 0402; Category : Capacitors (Size: 0402); Digikey P/N: 1276-1076-1-ND; Manufacturer: Samsung Electro-Mechanics; Part Num#: CL05A105KP5NNNC; Rating: 10V; SolidRun P/N: CA20005; Vol: 10%
C104 = CAP_NP1: CAP CER 10uF ±10% 16V X5R 0603; Category : Capacitors (Size: 0603); Digikey P/N: 490-10728-2-ND; Manufacturer: Murata Electronics North America; Part Num#: GRM188R61C106KAALD; Rating: 16V; SolidRun P/N: CA30014; Vol: 10%
C3 C6 C171 = CAP_NP1: CAP CER 4.7uF ±10% 10V X5R 0603; Category : Capacitors (Size: 0603); Digikey P/N: 311-1455-1-ND; Manufacturer: YAGEO; Part Num#: CC0603KRX5R6BB475; Rating: 10V; SolidRun P/N: CA30017; Vol: 10%
D29-D34 = LED: LED 2.1X0.6MM 570NM GRN RA SMD; Category: DI-LED; Digikey P/N: 754-1057-2-ND; Manufacturer: Kingbright Corp; Rating: 0.02A; SolidRun P/N: DI00250; Vol: 2.1V; Datasheet: http://www.kingbrightusa.com/images/catalog/SPEC/APA2106CGCK.pdf
J8 J10 = J-HEADER-8x1: 100 mil header 8 x 1; Category: CON-HEADER; Category : CON-HEADER; Manufacturer: cvilux; SolidRun P/N: CO00522; VOL: H=6.0; Datasheet: https://www.cvilux.com/uploads/catalog/p283%20CH31.pdf
J15 = J-uUSB-FCI: microUSB Type B connector; Category : CON-USB; Digikey P/N: 609-4050-2-ND; Manufacturer: Amphenol FCI; SolidRun P/N: CO00005; VOL: uUSB-B; Datasheet: https://cdn.amphenol-icc.com/media/wysiwyg/files/drawing/10103594.pdf
L1-L3 L5 L16 = Ferrite_Bead: Bead 120ohm, 100MHz, 2A; Category : COILS-FERRIT; Digikey P/N: 490-1037-2-ND; Manufacturer: Murata Electronics North America; Rating: 2A; SolidRun P/N: IN00003; Vol: 120Ohm_100M; Datasheet: https://www.murata.com/en-us/products/productdata/8796738650142/ENFA0003.pdf
Q1 = Mosfet_P: 20V P-Channel MOSFET; Category : TR-MOSFET-P; Digikey P/N: TSM2323CXRFGTR-ND; Manufacturer: Taiwan Semiconductor Corporation; SolidRun P/N: IC00666; Datasheet: http://www.taiwansemi.com/products/datasheet/TSM2323_F15.pdf
R40-R42 = RES1: RES SMD 4.7K OHM 5% 1/16W 0402; Category : Resistors (Size: 0402); Digikey P/N: 311-4.7KJRCT-ND; Manufacturer: YAGEO; Part Num#: RC0402JR-074K7L; Rating: 1/16W; SolidRun P/N: RE20002; Vol: 5%
R93 R94 R194-R199 = RES1: RES SMD 1.5K OHM 1% 1/16W 0402; Category : Resistors (Size: 0402); Manufacturer: THYE MING; Part Num#: CR-02FL6---1K5; Rating: 1/16W; SolidRun P/N: RE20029; Vol: 1%
R176 = RES1: RES SMD 2K OHM 5% 1/16W 0402; Category: Resistors (Size: 0402); Digikey P/N: 311-2.0KJRCT-ND; Manufacturer: YAGEO; Part Num#: RC0402JR-072KL; Rating: 1/16W; SolidRun P/N: RE20003; Vol: 5%
R186 R187 = RES1: RES SMD 39 OHM 1% 1/16W 0402; Category : Resistors (Size: 0402); Digikey P/N: 311-39.0LRCT-ND; Manufacturer: YAGEO; Part Num#: RC0402FR-0739RL; Rating: 1/16W; SolidRun P/N: RE20484; Vol: 1%
S2 = SW-TACT-2: Tactile Switches SMT Type 3.5*6; Category: Switches-TACT; Category : Switches-TACT; Manufacturer: DIPTRONICS; Rating: 0.05A; SolidRun P/N: CO00098; Vol: 12V; Datasheet: http://www.dip.com.tw/en/en-product-information/en-switch004/item/2444-dts-3-dtsm-l-3
SW1 SW2 = SW-SKSCLDE010: Tactile Switches 50 mAmps at 12 Volts; Category : Switches-TACT; Manufacturer: ALPS; Rating: 0.05A; SolidRun P/N: SW00001; Vol: 12V; Datasheet: https://www.mouser.co.il/datasheet/2/15/SKSC-1370794.pdf
U7 = IC-AT24C02D: I2C Compatible Serial EEPROM  2-Kbit (256 x 8); Category : IC-MEM-EEPROM; Digikey P/N: AT24C02D-SSHM-B-ND; Manufacturer: Microchip Technology; SolidRun P/N: IC00927; VOL: 2Kbit; Datasheet: http://www.microchip.com/mymicrochip/filehandler.aspx?ddocname=en590275
U10 = IC-TS3A5223RSWR: Dual analog switch - SPDT; Category : IC-ANG; Digikey P/N: 296-35687-2-ND; Manufacturer: Texas Instruments; SolidRun P/N: IC00220; VOL: SPDT; Datasheet: http://www.ti.com/lit/ds/symlink/ts3a5223.pdf
U11 = IC-TS9011DCX: LDO - 1.8V output, 0.25A, 12V maximum in; Category : IC-PWR-LDO; Digikey P/N: TS9011DCXRFG-ND; Manufacturer: Taiwan Semiconductor Corporation; Rating: 0.25A; SolidRun P/N: IC00014; VOL: 1.8V; Datasheet: http://www.taiwansemi.com/products/datasheet/TS9011_H1608.pdf
U17 = J-uSD-ZM90: SD/MMC card connector Push-Push/CD; Category : CON-Usd/SIM; Manufacturer: CEN LINK; SolidRun P/N: CO00091; Datasheet: http://www.cenlink.com.tw/upload/20120718204404.pdf
U25 = IC-Dual_Buffer: Dual Buffer - NLX2G16; Category: IC-LOGIC; Manufacturer: ON Semiconductor; SolidRun P/N: IC00300
U26 = IC-FT230XQ-R: FT230XQ-R - uUSB to UART converter; Category : IC-USB; Digikey P/N: 768-1130-2-ND; Manufacturer: FTDI, Future Technology Devices International Ltd; SolidRun P/N: IC00015; Datasheet: http://www.ftdichip.com/Support/Documents/DataSheets/ICs/DS_FT230X.pdf
C1 C109 = CAP_NP1: CAP CER 47uF ±20% 10V X5R 1206; Category : Capacitors (Size: 1206); Digikey P/N: 587-3428-1-ND; Manufacturer: Taiyo Yuden; Part Num#: LMK316ABJ476ML-T; Rating: 10V; SolidRun P/N: CA50008; Vol: 20%
C31 = CAP_NP1: CAP CER 22pF ±5% 50V C0G/NP0 0402; Category: Capacitors (Size: 0402); Digikey P/N: 490-5868-1-ND; Manufacturer: Murata Electronics North America; Part Num#: GRM1555C1H220JA01D; Rating: 50V; SolidRun P/N: CA20080; Vol: 5%
C125 C139 C140 = CAP_NP1: CAP CER 0.01uF ±10% 10V X7R 0402; Category : Capacitors (Size: 0402); Digikey P/N: 311-1703-1-ND; Manufacturer: YAGEO; Part Num#: CC0402KRX7R6BB103; Rating: 10V; SolidRun P/N: CA20081; Vol: 10%
CON3 = J-Dual_USB3: Category : CON-USB; Manufacturer: Antek (Cidev); SolidRun P/N: CO00554; Datasheet: http://www.antenk.com/cpxx.asp?flag=392&id=1824
D1 D5 = TVS-BI: TVS DIODE 5VWM SOD523 BI; Category : DI-TVS; Digikey P/N: ESD5B5.0ST1GOSTR-ND; Manufacturer: ON Semiconductor; Rating: 50W; SolidRun P/N: DI00242; Vol: 5V (5.8/7.8}; Datasheet: http://www.onsemi.com/pub/Collateral/ESD5B5.0ST1-D.PDF
D3 D6 = Diode-STK-OLD: DIODE SCHOTTKY 40V 500MA 2DSN; Category : DI-Diode; Digikey P/N: NSR05F40NXT5GOSTR-ND; Manufacturer: ON Semiconductor; Rating: 0.5A; SolidRun P/N: DI00237; Vol: 40V; Datasheet: http://www.onsemi.com/pub/Collateral/NSR05F40-D.PDF
L9 = INDUCTOR1: FIXED IND 1UH 3.4A 56 MOHM SMD 2.5 x 2.0; Category: COILS-IND; Digikey P/N: 445-173025-2-ND; Manufacturer: TDK Corporation; Rating: 3.4A; SolidRun P/N: IN00096; Vol: 1uH; Datasheet: https://product.tdk.com/info/en/catalog/datasheets/inductor_commercial_power_vls252012hbx-1_en.pdf
R6 R100 = RES1: RES SMD 24K OHM 1% 1/16W 0402; Category : Resistors (Size: 0402); Digikey P/N: 541-24.0KLCT-ND; Manufacturer: VISHAY; Part Num#: CRCW040224K0FKED; Rating: 1/16W; SolidRun P/N: RE20038; Vol: 1%
R13 R15 = RES1: RES SMD 100K OHM 1% 1/16W 0402; Category: Resistors (Size: 0402); Digikey P/N: 311-100KLRCT-ND; Manufacturer: YAGEO; Part Num#: RC0402FR-07100KL; Rating: 1/16W; SolidRun P/N: RE20482; Vol: 1%
R116 = RES1: RES SMD 200 OHM 1% 1/16W 0402; Category : Resistors (Size: 0402); Manufacturer: THYE MING; Part Num#: CR02FL6--200R; Rating: 1/16W; SolidRun P/N: RE20032; Vol: 1%
R131 = RES1: RES SMD 6.04K OHM 1% 1/16W 0402; Category : Resistors (Size: 0402); Digikey P/N: YAG2293CT-ND; Manufacturer: YAGEO; Part Num#: RC0402FR-076K04L; Rating: 1/16W; SolidRun P/N: RE20004; Vol: 1%
TP1 TP2 = T_POINT_R: TEST POINT MINIATURE SMT; AGILE_PN: 510-75618; CAD_APPROVED: Yes; Category : Test Point; HEIGHT: 0.1MM; ROHS: Yes
U1 U4 = IC-NX5P3090UK_WLCSP12: IC PWR SWITCH 1:1 12WLCSP; Category : IC-PWR-SW; Digikey P/N: 568-13049-2-ND; Manufacturer: NXP USA Inc; Rating: 3.3A; SolidRun P/N: IC01183; VOL: 5.5V; Datasheet: https://www.nxp.com/docs/en/data-sheet/NX5P3090.pdf
U3 U19 = D-PCMF3USB3S: CMC 6LN SMD ESD USB 3.1, USB 2.0, HDMI 2.0, HDMI 1.4; Category : DI-TVS; Digikey P/N: 1727-2510-2-ND; Manufacturer: Nexperia USA Inc.; Rating: 7A; SolidRun P/N: DI00239; Vol: 5V(6/9); Datasheet: https://assets.nexperia.com/documents/data-sheet/PCMFXUSB3S_SER.pdf
U20 = IC-AP3441: Buck Switching Regulator IC Positive Adjustable 0.6V 1 Output 3A 8-VFDFN Exposed Pad; Category: IC-PWR-BUCK; Digikey P/N: AP3441LSHE-7B-ND; Manufacturer: Diodes Incorporated; Rating: 3A; SolidRun P/N: IC01417; VOL: 2.7-5.5V; Datasheet: https://www.diodes.com/assets/Datasheets/AP3441-L.pdf
U22 = IC-CYUSB3304-68LTXC: IC USB 3.0 HUB 4-PORT 68QFN; Category : IC-USB; Digikey P/N: 428-3331-ND; Manufacturer: Cypress Semiconductor Corp; SolidRun P/N: IC01162; Datasheet: http://www.cypress.com/file/141031/download
Y2 = XTAL-4P: 26MHz ±10ppm Crystal 12pF 60 Ohms; Category : OC-CRYSTAL; Digikey P/N: SER4186TR-ND; Manufacturer: EPSON; Rating: 12pF/10PPM; SolidRun P/N: OC00025; Datasheet: https://support.epson.biz/td/api/doc_check.php?dl=brief_FA-128_en.pdf

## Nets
GND: B1.2(-) C1.2 C2.2 C3.2 C6.2 C7.2 C14.2 C17.2 C18.2 C32.2 C40.2 C41.2 C46.2 C47.2 C48.2 C50.2 C51.2 C52.2 C53.2 C54.2 C56.1 C62.2 C63.2 C64.2 C65.2 C68.2 C69.2 C70.2 C72.1 C74.2 C78.2 C79.2 C80.2 C89.2 C96.2 C99.2 C102.2 C103.2 C104.2 C105.2 C108.2 C109.2 C112.2 C114.2 C125.2 C126.2 C127.2 C128.2 C129.2 C130.2 C131.2 C132.2 C133.2 C134.2 C135.2 C136.1 C138.2 C139.2 C140.2 C141.2 C145.2 C152.2 C153.2 C170.2 C171.2 C173.2 C176.2 C177.2 C178.2 C179.2 C180.2 C181.2 C182.2 C183.2 C184.2 C185.2 CON3.4(GND) CON3.7(GND) CON3.13(GND) CON3.16(GND) D1.1 D5.1 FB1.1 FB2.2 J8.8 J10.8 J15.5(GND) J15.6(SH1) J15.7(SH2) J15.SH1(SH4) J15.SH2(SH3) J18.C5 J20.4(GND4) J20.9(GND9) J20.15(GND15) J20.18(GND18) J20.21(GND21) J20.26(GND26) J20.27(GND27) J20.29(GND29) J20.34(GND34) J20.35(GND35) J20.37(GND37) J20.40(GND40) J20.43(GND43) J20.50(GND50) M1.3 M1.5 M1.11 M1.21 M1.27 M1.33 M1.39 M1.45 M1.51 M1.57 M1.71 M1.73 R6.2 R13.2 R21.2 R29.2 R57.2 R65.2 R67.2 R82.2 R84.2 R88.2 R98.2 R100.2 R110.1 R111.2 R116.1 R118.2 R124.2 R127.2 R131.1 R132.2 R133.2 R137.1 R138.2 R139.2 R152.2 R154.2 R178.2 R194.2 S2.1 SW1.1 SW1.2 SW2.1 SW2.2 U1.B3(GND1) U1.C3(GND2) U1.D3(GND3) U3.B1(GND_CH1) U3.B2(GND_CH2) U3.B3(GND_CH3) U4.B3(GND1) U4.C3(GND2) U4.D3(GND3) U5.16(GND) U5.21(PAD) U7.4(GND) U8.3(AGND) U8.10(PGND1) U8.11(PGND2) U8.12(PGND3) U9.3(AGND) U9.10(PGND1) U9.11(PGND2) U9.12(PGND3) U10.6(GND) U11.1(GND) U13.1(GND) U17.6(VSS1) U17.G1 U17.G2 U17.G3 U17.G4 U19.B1(GND_CH1) U19.B2(GND_CH2) U19.B3(GND_CH3) U20.4(PGND) U20.8(SGND) U20.9(PAD) U21.2(WDI) U21.3(nEXTR) U21.9(VSS) U21.10(EXTI) U21.17(EPAD) U22.40(GND) U22.69(EPAD) U23.16(GND) U23.21(PAD) U25.2(GND) U26.3(AGND) U26.13(GND) U26.17(PAD) Y2.2 Y2.4 ; also on sheet 5 6 7 8 9 10
GNDC: CON1.2(GND[0]) CON1.3(GND[1]) CON3.SH1 CON3.SH2 CON3.SH3 CON3.SH4 FB1.2 FB2.1 J2.1 ; also on sheet 5 7 8 10
VCC_1P8: C74.1 U10.2(NO1) U11.2(Vout)
VDD_3V3: C40.1 C112.1 C176.1 C177.1 C178.1 D29.A D30.A D31.A D32.A D33.A D34.A J8.7 L3.1 Q1.S R4.1 R9.1 R40.2 R41.2 R42.2 R81.2 R93.2 R94.2 R99.1 R113.1 R114.1 R117.1 R120.1 R121.1 R122.1 R134.1 R135.1 R151.1 R175.1 R176.1 R202.2 U7.8(VCC) U10.1(VCC) U10.5(NC1) U11.3(Vin) U20.3(VIN) U22.56(AVDD33_6) U22.61(AVDD33_7) U22.66(AVDD33_8) U25.5(VCC) ; also on sheet 5 6 7 8 9 10
VDD_USB_1V2: C31.1 C62.1 C114.1 C125.1 C126.1 C141.1 C179.1 C180.1 C181.1 C182.1 C183.1 C184.1 C185.1 L5.1 L9.2 R15.1 U22.7(DVDD12_4) U22.10(AVDD12_1) U22.13(DVDD12_5) U22.16(AVDD12_2) U22.34(AVDD12_3) U22.37(DVDD12_6) U22.43(DVDD12_7) U22.46(AVDD12_4) U22.49(DVDD12_8) U22.52(AVDD12_5) U22.53(AVDD12_6)
VIN: C41.1 C52.1 C53.1 C69.1 C70.1 R128.1 R136.1 R140.1 R153.1 R156.1 SH4.2 SH5.2 U5.4(VOUT) U5.5(VOUT) U5.6(VOUT) U5.7(VOUT) U5.8(VOUT) U8.4(IN1) U8.5(IN2) U8.6(IN3) U8.7(IN4) U8.8(IN5) U9.4(IN1) U9.5(IN2) U9.6(IN3) U9.7(IN4) U9.8(IN5) U23.4(VOUT) U23.5(VOUT) U23.6(VOUT) U23.7(VOUT) U23.8(VOUT) ; also on sheet 9
VIN_JACK: C14.1 C18.1 FB3.2 R16.1 SH5.1 U5.9(VIN) U5.10(VIN) U5.11(VIN) U5.12(VIN) U5.13(VIN)
DCDC_5V: C1.1 C7.1 C78.1 C79.1 C80.1 C108.1 C109.1 J10.7 L7.2 R3.1 R11.1 R157.1 U1.B1(VINT1) U1.B2(VINT2) U1.C1(VINT3) U4.B1(VINT1) U4.B2(VINT2) U4.C1(VINT3) ; also on sheet 5 8 9 10
DMODE: R22.1 R140.2 U23.2(PGOOD)
DPR: M1.25 R98.1 R102.2
ECSPI2_MISO: J8.5 ; also on sheet 8
ECSPI2_MOSI: J8.6 ; also on sheet 8
ECSPI2_SCLK: J8.4 ; also on sheet 8
ECSPI2_SS0: J8.3 ; also on sheet 8
Full_Card_Power_Off#: M1.6 R32.2
GPIO1: R195.2 ; also on sheet 8
HUB_MODE0: R118.1 R120.2 U22.23(MODE_SEL[0])
HUB_MODE1: R117.2 U22.24(MODE_SEL[1])
HUB_RSTN: C129.1 R109.2 R113.2 U22.31(RESETN)
I2C2_SCL: U22.32(I2C_CLK) ; also on sheet 6 8
I2C2_SDA: U22.33(I2C_DATA) ; also on sheet 6 8
I2C3_SCL: J10.5 U7.6(SCL) U21.7(SCL) ; also on sheet 7 8 9 10
I2C3_SDA: J10.6 U7.5(SDA) U21.6(SDA) ; also on sheet 7 8 9 10
M2_3V3: C63.1 C64.1 C65.1 C99.1 C133.1 D8.A D11.A J20.2(3V3) J20.24(3V3) J20.39(3V3) J20.41(3V3) J20.52(3V3) L6.2 M1.2 M1.4 M1.70 M1.72 M1.74 R32.1 R85.1 R102.1 R125.1 U13.3(Vin)
M.2_GPS_EN#: M1.26 ; also on sheet 8
M.2_PCIe_3V3_EN: R123.1 ; also on sheet 8
M.2_RESET#: M1.67 ; also on sheet 8
M.2_W_DIS#: M1.8 ; also on sheet 8
M.2_WAKW_ON_LAN: M1.23 ; also on sheet 8
Mini-PCIe_PREST#: J20.22(PERST#) R65.1 ; also on sheet 8
Mini-PCIe_W_DIS#: R158.2 ; also on sheet 8
NVCC_SD2: C68.1 R151.2 U10.3(COM1) ; also on sheet 8
ONOFF: SW1.3 SW1.4 ; also on sheet 8
PCIE1_REF_CLKN_CN: C150.1 ; also on sheet 8
PCIE1_REF_CLKP_CN: C151.1 ; also on sheet 8
PCIE1_RXN_C: C154.1 ; also on sheet 8
PCIE1_RXP_C: C155.1 ; also on sheet 8
PCIE1_TXN_C: C156.1 ; also on sheet 8
PCIE1_TXP_C: C161.1 ; also on sheet 8
PCIe_UIM_CLK: J18.C3 J20.12(UIM_CLK) M1.32
PCIe_UIM_DATA: J18.C7 J20.10(UIM_DATA) M1.34
PCIe_UIM_PWR: C130.1 C131.1 J18.C1 J20.8(UIM_PWR) M1.36
PCIe_UIM_RST: J18.C2 J20.14(UIM_RST) M1.30
PDPR: J20.44(LED_WLAN#) R84.1 R85.2
POE_VIN_12V: R126.1 SH4.1 U23.9(VIN) U23.10(VIN) U23.11(VIN) U23.12(VIN) U23.13(VIN) ; also on sheet 7
PWM2_OUT: Q1.G R67.1 ; also on sheet 8
PWWAN_LED#: D11.C J20.42(LED_WWAN#)
RTC_CLKO: U21.8(CLKOUT/nIRQ3) ; also on sheet 8
RXD: R176.2 U25.3(IN_A2) U26.15(TXD)
SAI2_RXD: J8.2 ; also on sheet 6 8
SD2_CLK: U17.5(CLK) ; also on sheet 8
SD2_CMD: U17.3(CMD) ; also on sheet 8
SD2_DATA0: U17.7(D0) ; also on sheet 8
SD2_DATA1: U17.8(D1) ; also on sheet 8
SD2_DATA2: U17.1(D2) ; also on sheet 8
SD2_DATA3: U17.2(CD/D3) ; also on sheet 8
SD2_nCD: U17.9(Cd) ; also on sheet 8
SD2_VSELECT: R57.1 U10.4(SEL1) ; also on sheet 8
SYS_nRST: S2.2 SW2.3 SW2.4 ; also on sheet 8
TERMINAL_RX: R175.2 U25.4(OUT_Y2) ; also on sheet 8
TERMINAL_TX: U25.1(IN_A1) ; also on sheet 8
TXD: U25.6(OUT_Y1) U26.2(RXD)
UART2_CTS: R197.2 ; also on sheet 8
UART2_RTS: R196.2 ; also on sheet 8
UART2_RXD: R199.2 ; also on sheet 8
UART2_TXD: R198.2 ; also on sheet 8
UART3_CTS: J10.1 ; also on sheet 8
UART3_RTS: J10.2 ; also on sheet 8
UART3_RXD: J10.3 ; also on sheet 8
UART3_TXD: J10.4 ; also on sheet 8
USB1_DN: R104.1 ; also on sheet 8
USB1_DP: R103.1 ; also on sheet 8
USB1_PWR_EN: D6.2(ANODE) R11.2 R99.2 U4.A1(EN) ; also on sheet 8
USB1_RXN: U19.A3(CH2_IN+) ; also on sheet 8
USB1_RXP: U19.A4(CH2_IN-) ; also on sheet 8
USB1_TXN: C111.1 ; also on sheet 8
USB1_TXP: C110.1 ; also on sheet 8
USB1_VBUS: C6.1 C17.1 CON3.10(VBUS2) D5.2 L2.2 ; also on sheet 8
USB2_DN: U22.58(US_DM) ; also on sheet 8
USB2_DP: U22.57(US_DP) ; also on sheet 8
USB2_RXN: C146.1 ; also on sheet 8
USB2_RXP: C147.1 ; also on sheet 8
USB2_TXN: C148.1 ; also on sheet 8
USB2_TXP: C149.1 ; also on sheet 8
USB2_VBUS: R132.1 R135.2 U22.17(VBUS_US) ; also on sheet 8
USB-HUB_RST#: R109.1 ; also on sheet 8
USB_HOST1_DN: CON3.2(D1-) U3.C1(CH1_OUT+)
USB_HOST1_DP: CON3.3(D1+) U3.C2(CH1_OUT-)
USB_HOST1_RXN: CON3.5(SSRX1-) U3.C4(CH2_OUT-)
USB_HOST1_RXP: CON3.6(SSRX1+) U3.C3(CH2_OUT+)
USB_HOST1_TXN: CON3.8(SSTX1-) U3.C5(CH3_OUT+)
USB_HOST1_TXP: CON3.9(SSTX1+) U3.C6(CH3_OUT-)
USB_HOST1_VBUS: C2.1 C3.1 CON3.1(VBUS1) D1.2 L1.2
USB_HOST2_DN: CON3.11(D2-) U19.C1(CH1_OUT+)
USB_HOST2_DP: CON3.12(D2+) U19.C2(CH1_OUT-)
USB_HOST2_RXN: CON3.14(SSRX2-) U19.C3(CH2_OUT+)
USB_HOST2_RXP: CON3.15(SSRX2+) U19.C4(CH2_OUT-)
USB_HOST2_TXN: CON3.17(SSTX2-) U19.C5(CH3_OUT+)
USB_HOST2_TXP: CON3.18(SSTX2+) U19.C6(CH3_OUT-)
USB_HOSTDS1_DN: R10.1 U22.59(DS1_DM)
USB_HOSTDS1_DP: R14.1 U22.60(DS1_DP)
USB_HOSTDS2_DN: M1.9 U22.63(DS2_DM)
USB_HOSTDS2_DP: M1.7 U22.62(DS2_DP)
USB_HOSTDS3_DN: J20.36(USB_D-) U22.64(DS3_DM)
USB_HOSTDS3_DP: J20.38(USB_D+) U22.65(DS3_DP)
USB_HUB_CH1_PWR_EN: D3.2(ANODE) R3.2 R4.2 U1.A1(EN) ; also on sheet 8
USBDS1_RX_N: U3.A4(CH2_IN-) U22.50(DS1_RXM)
USBDS1_RX_P: U3.A3(CH2_IN+) U22.51(DS1_RXP)
USBDS1_TX_N: C16.1 U22.48(DS1_TXM)
USBDS1_TX_P: C5.1 U22.47(DS1_TXP)
USBDS2_RX_N: C11.1 U22.44(DS2_RXM)
USBDS2_RX_P: C10.1 U22.45(DS2_RXP)
USBDS2_TX_N: C9.1 U22.42(DS2_TXM)
USBDS2_TX_P: C8.1 U22.41(DS2_TXP)
USBDS3_RX_N: C76.1 U22.36(DS3_RXM)
USBDS3_RX_P: C77.1 U22.35(DS3_RXP)
USBDS3_TX_N: C82.1 U22.39(DS3_TXM)
USBDS3_TX_P: C85.1 U22.38(DS3_TXP)
V_1P5: C96.1 J20.6(1V5) J20.28(1V5) J20.48(1V5) R88.1 U13.2(Vout)
V_DCJACK_IN: CON1.1(V) FB3.1 J2.2
V_SD: C89.1 Q1.D R81.1 R82.1 U17.4(VDD)
VUSB_IN: C104.1 C105.1 J15.1(VBUS) L16.1 R184.1
WIFI_DN: U22.68(DS4_DM) ; also on sheet 8
WIFI_DP: U22.67(DS4_DP) ; also on sheet 8
WWAN_LED#: D8.C M1.10
N339767: R10.2 U3.A1(CH1_IN+)
N339781: R14.2 U3.A2(CH1_IN-)
N339891: C16.2 U3.A5(CH3_IN+)
N339905: C5.2 U3.A6(CH3_IN-)
N341837: R104.2 U19.A1(CH1_IN+)
N341853: R103.2 U19.A2(CH1_IN-)
N341969: C111.2 U19.A5(CH3_IN+)
N341985: C110.2 U19.A6(CH3_IN-)
N356029: L1.1 U1.C2(VBUS1) U1.D1(VBUS2) U1.D2(VBUS3)
N356255: D3.1(CATHODE) U1.A2(~{FAULT})
N356259: R6.1 U1.A3(ILIM)
N357373: L2.1 U4.C2(VBUS1) U4.D1(VBUS2) U4.D2(VBUS3)
N357595: D6.1(CATHODE) U4.A2(~{FAULT})
N357599: R100.1 U4.A3(ILIM)
N384972: C11.2 M1.29
N384976: C10.2 M1.31
N385154: C9.2 M1.35
N385158: C8.2 M1.37
N432703: C170.1 C171.1 L16.2 U26.10(VCC)
N432793: C102.1 J15.2(DM) R187.1
N432805: R187.2 U26.7(USB_DM)
N432825: C103.1 J15.3(DP) R186.1
N432865: R186.2 U26.6(USB_DP)
N432869: R177.2 U26.16(RTS)
N432945: R177.1 U26.4(CTS)
N432959: C173.1 R188.1 U26.1(VCCIO) U26.8(3V3OUT)
N432967: R188.2 U26.9(Reset)
N433007: R178.1 R184.2 U26.12(CBUS0)
N433039: D19.A U26.11(CBUS1)
N433047: D18.A U26.5(CBUS2)
N433175: D19.C R94.1
N542724: C82.2 C156.2 J20.31(PETn0)
N542728: C85.2 C161.2 J20.33(PETp0)
N619182: B1.1(+) C138.1 R115.2
N619188: R115.1 U21.5(VBAT)
N619554: C127.1 U21.16(XI) Y3.1
N619560: C132.1 U21.15(XO) Y3.2
N619626: C136.2 U21.14(AF)
N620183: C135.1 R202.1 U21.13(VCC)
N641587: D18.C R93.1
N858969: R40.1 U7.1(A0)
N858976: R41.1 U7.2(A1)
N858989: R42.1 U7.3(A2)
N961959: R29.1 U7.7(WP)
N963208: C150.2 J20.11(REFCLK-)
N963216: C151.2 J20.13(REFCLK+)
N963376: C76.2 C154.2 J20.23(PERn0)
N963384: C77.2 C155.2 J20.25(PERp0)
N1030509: C50.1 C51.1 C139.1 L5.2 U22.1(DVDD12) U22.3(DVDD12_2) U22.19(VDD_EFUSE) U22.27(DVDD12_3)
N1030566: C46.1 C47.1 C140.1 L3.2 U22.4(AVDD33_9) U22.28(VDD_IO)
N1211594: TP1.1(TP) U22.29(PWR_EN)
N1238958: C32.1 U5.18(dVdT)
N1238966: R21.1 U5.19(IMON)
N1238990: R111.1 U5.17(ILIM)
N1264830: R138.1 U23.17(ILIM)
N1264938: C145.1 U23.18(dVdT)
N1265251: R139.1 U23.19(IMON)
N1265408: R127.1 R128.2 U23.3(PGTH)
N1265747: R126.2 U23.14(EN/UVLO)
N1266663: R16.2 U5.14(EN/UVLO)
N1293059: J20.20(W_DIS#) R158.1
N1318309: R22.2 U5.1(DMODE)
N3852981: R137.2 U23.15(OVP)
N3853546: R110.2 U5.15(OVP)
N4070800: C55.1 U8.16(BST)
N4070804: C55.2 L6.1 U8.9(LX1) U8.13(LX2) U8.14(LX3)
N4071248: R124.1 R125.2 U8.2(FB)
N4071318: C48.1 U8.18(SS)
N4072908: C71.2 L7.1 U9.9(LX1) U9.13(LX2) U9.14(LX3)
N4073152: R154.1 R157.2 U9.2(FB)
N16560234: D29.C R194.1
N16560734: D30.C R195.1
N16560938: D31.C R196.1
N16561141: D32.C R197.1
N16561345: D33.C R198.1
N16561546: D34.C R199.1
N16589455: C56.2 U8.17(VCC)
N16592243: C72.2 U9.17(VCC)
N16592259: C153.1 U9.18(SS)
N16592643: C71.1 U9.16(BST)
N16594128: C152.1 R156.2 U9.15(TON)
N16594606: C54.1 R136.2 U8.15(TON)
N16594972: R152.1 R153.2 U9.1(EN)
N17127518: R123.2 U8.1(EN)
N17198811: L9.1 U20.6(LX)
N17198847: C31.2 R13.1 R15.2 U20.1(FB)
N17200093: R9.2 U20.7(EN)
N18609057: C146.2 U22.5(US_TXM)
N18609067: C147.2 U22.6(US_TXP)
N105578872: C128.1 U22.54(XTL_OUT) Y2.1
N105578933: C134.1 U22.55(XTL_IN) Y2.3
N105579362: R121.2 U22.21(SWDDIO)
N105579373: R122.2 U22.22(SWDCLK)
N105704268: R114.2 U22.30(OVRCURR)
N105704492: TP2.1(TP) U22.20(SUSPEND)
N105704755: R116.2 U22.26(RREF_SS)
N105704758: R131.2 U22.2(RREF_USB2)
N105705743: C148.2 U22.8(US_RXM)
N105705746: C149.2 U22.9(US_RXP)
N106175198: R133.1 R134.2 U22.18(VBUS_DS)

Not connected (* = marked no-connect by the designer): J4 1; J5 1; J6 1; J8 1; J15 4(ID)*; J18 C6; J20 1(WAKE#) 3(COEX1) 5(COEX2) 7(CLKREQ#) 16(UIM_VPP) 17(RSV17) 19(RSV19) 30(SMB_CLK) 32(SMB_DATA) 45(RSV45) 46(LED_WPAN#) 47(RSV47) 49(RSV49) 51(RSV51); M1 1 12 13 14 15 16 17 18 19 20 22 24 28 38 40 41 42 43 44 46 47 48 49 50 52 53 54 55 56 58 59 60 61 62 63 64 65 66 68 69 75; U5 2(PGOOD)* 3(PGTH)* 20(~{FLT})*; U10 7(NC2) 8(SEL2) 9(COM2) 10(NO2); U20 2(PG) 5(NC)*; U21 1(nRST)* 4(PSW/nIRQ2)* 11(FOUT/nIRQ) 12(nTIRQ)*; U22 11(DS4_TXP)* 12(DS4_TXM)* 14(DS4_RXM)* 15(DS4_RXP)* 25(GPIO); U23 1(DMODE)* 20(~{FLT})*; U26 14(CBUS3)

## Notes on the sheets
sheet 1
- SH4, SH5 bypass U40 and U41 when Vin is
  a sigle source (Adapter or POE)
- 3V3/6A powers the M.2 and Mini-PCIe modules
- 5V/6A powers the SOM and USB power out
- R1
- R1
- R2
- R2
- VO = 0.8 x (1 + R1/R2)
- VO = 0.8 x (1 + R1/R2)
sheet 2
- micro SD connectors (assembly option of push-push type and hinged type)
- SDIO 3.3v / 1.8v switch circuitry
- micro SD power on/off
- RESET button
- DEBUG/Control PORT
- RESET button
- Micro USB Type A/B
- USB to RS-232
- TX Data
- RX Data
- DM00002
sheet 3
- 3.3v to 1.5v LDO (for mini pci express)
- J15 and J16 mini pcie
  outer mechanical holes
- MECH_X_Y is a mechanical hole that the hole size is X mm and padstack is Y mm.
  J4 and J20 are for mini PCI-e half size
  J15 and J16 are for mini PCI-e full size
  4 of those mechanical holes are suitable for M2.5
- WAKE_ON_WAN#
- GPS_DISABLE#, PU
- RESET# (1V8)
sheet 4
- 1,1 - Internal ROM
- Address 0x60
- VO = 0.6 x (1 + R1/R2)
- ~2.1A Power Limit
- 2.1A
- ~2.1A Power Limit
- 2.1A
